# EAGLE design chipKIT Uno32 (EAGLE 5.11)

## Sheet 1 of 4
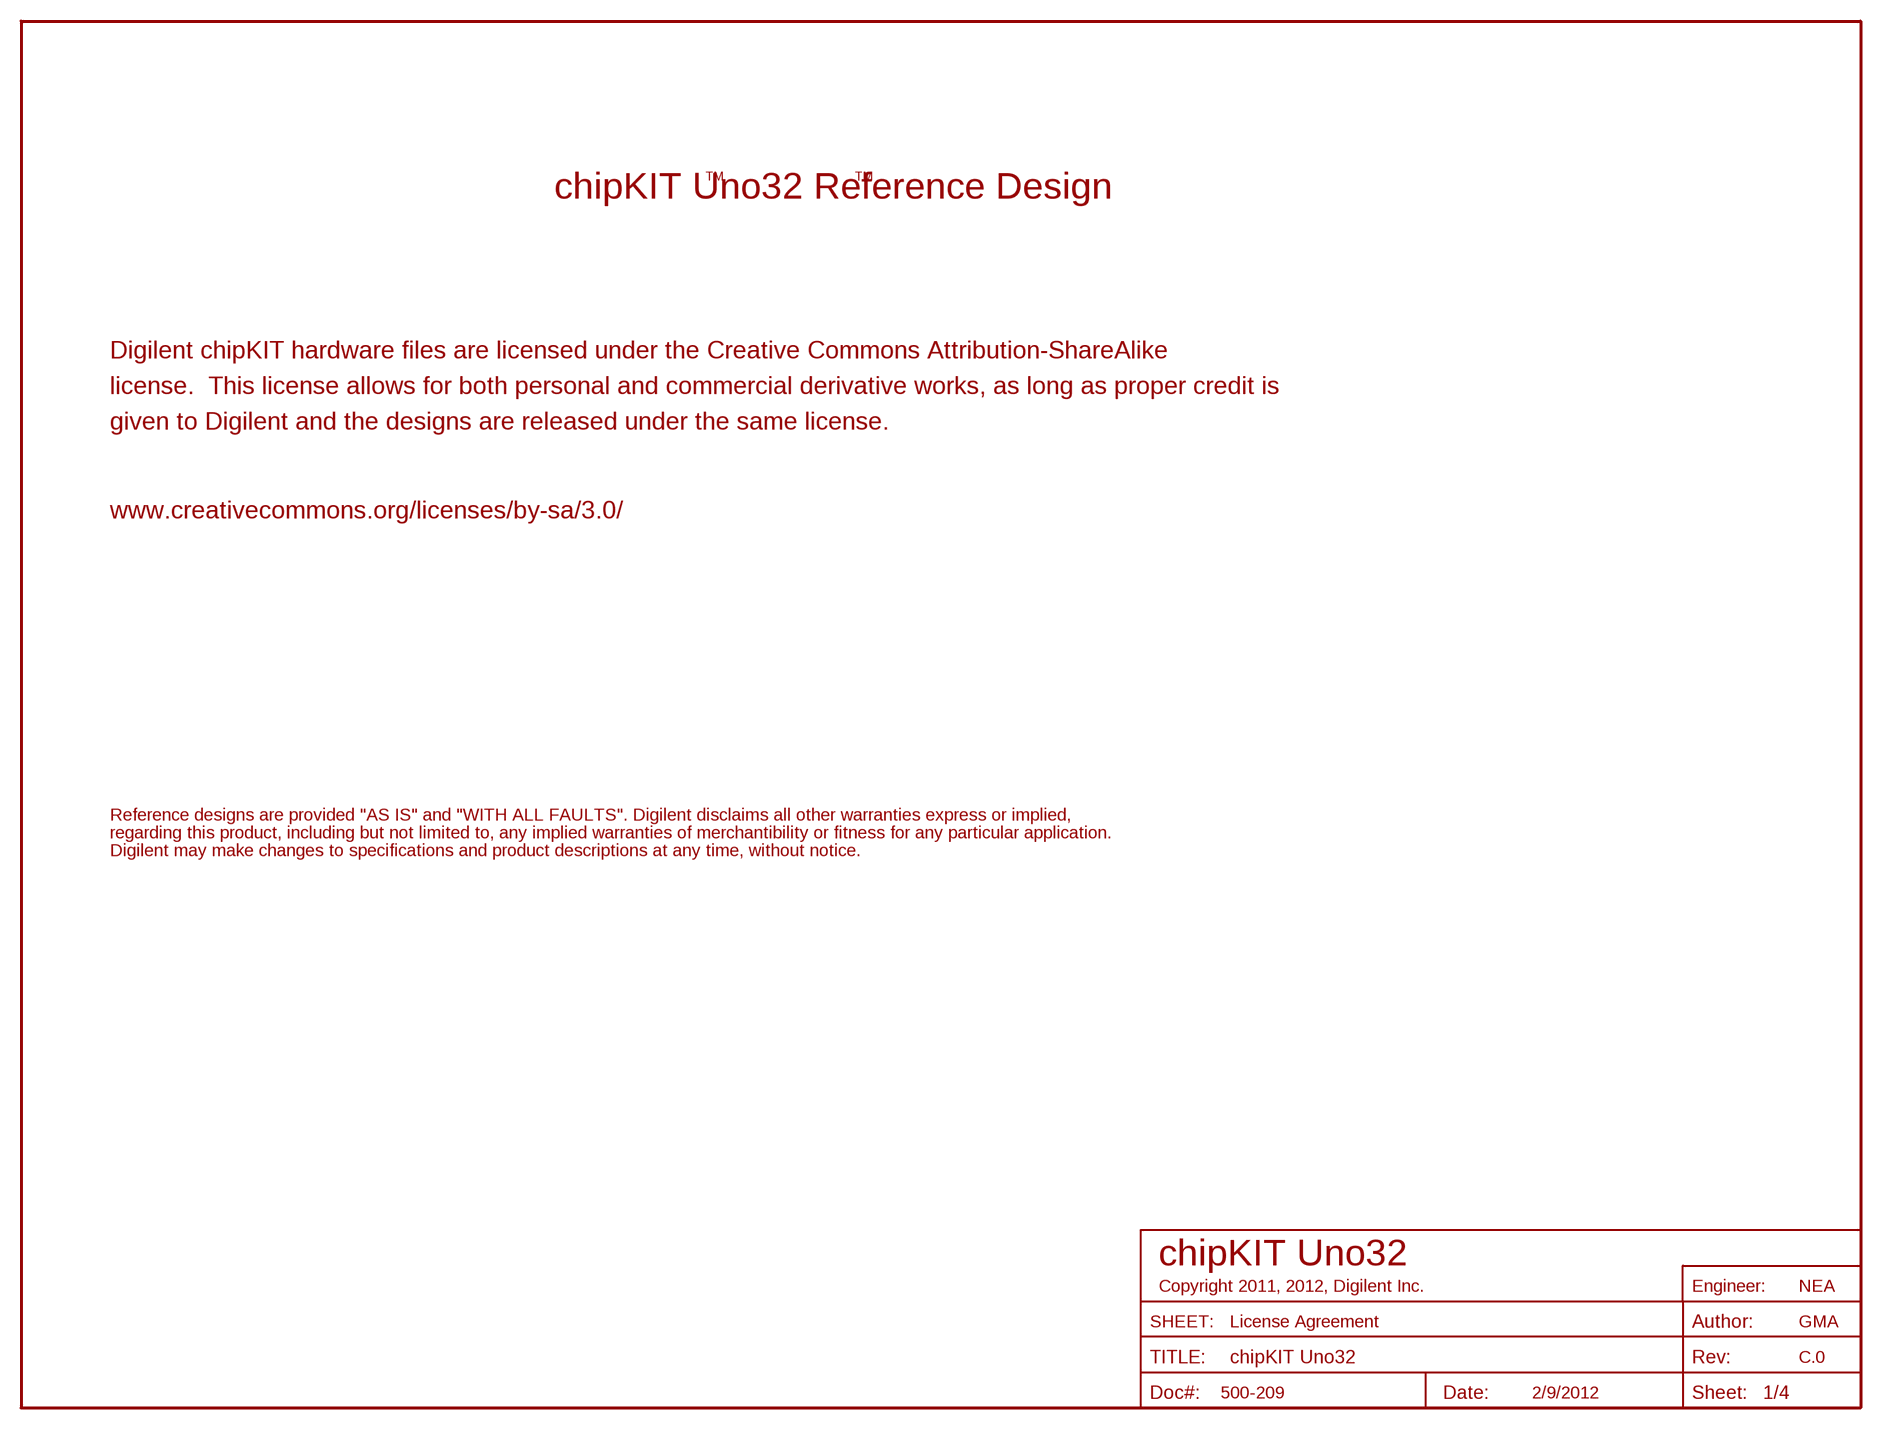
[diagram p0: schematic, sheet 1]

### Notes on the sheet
- TM | TM
- chipKIT Uno32 Reference Design
- Digilent chipKIT hardware files are licensed under the Creative Commons Attribution-ShareAlike
- license.  This license allows for both personal and commercial derivative works, as long as proper credit is
- given to Digilent and the designs are released under the same license.
- www.creativecommons.org/licenses/by-sa/3.0/
- Reference designs are provided "AS IS" and "WITH ALL FAULTS". Digilent disclaims all other warranties express or implied,
- regarding this product, including but not limited to, any implied warranties of merchantibility or fitness for any particular application.
- Digilent may make changes to specifications and product descriptions at any time, without notice.
- chipKIT Uno32
- Copyright 2011, 2012, Digilent Inc. | NEA
- License Agreement | GMA
- C.0
- 500-209 | 2/9/2012

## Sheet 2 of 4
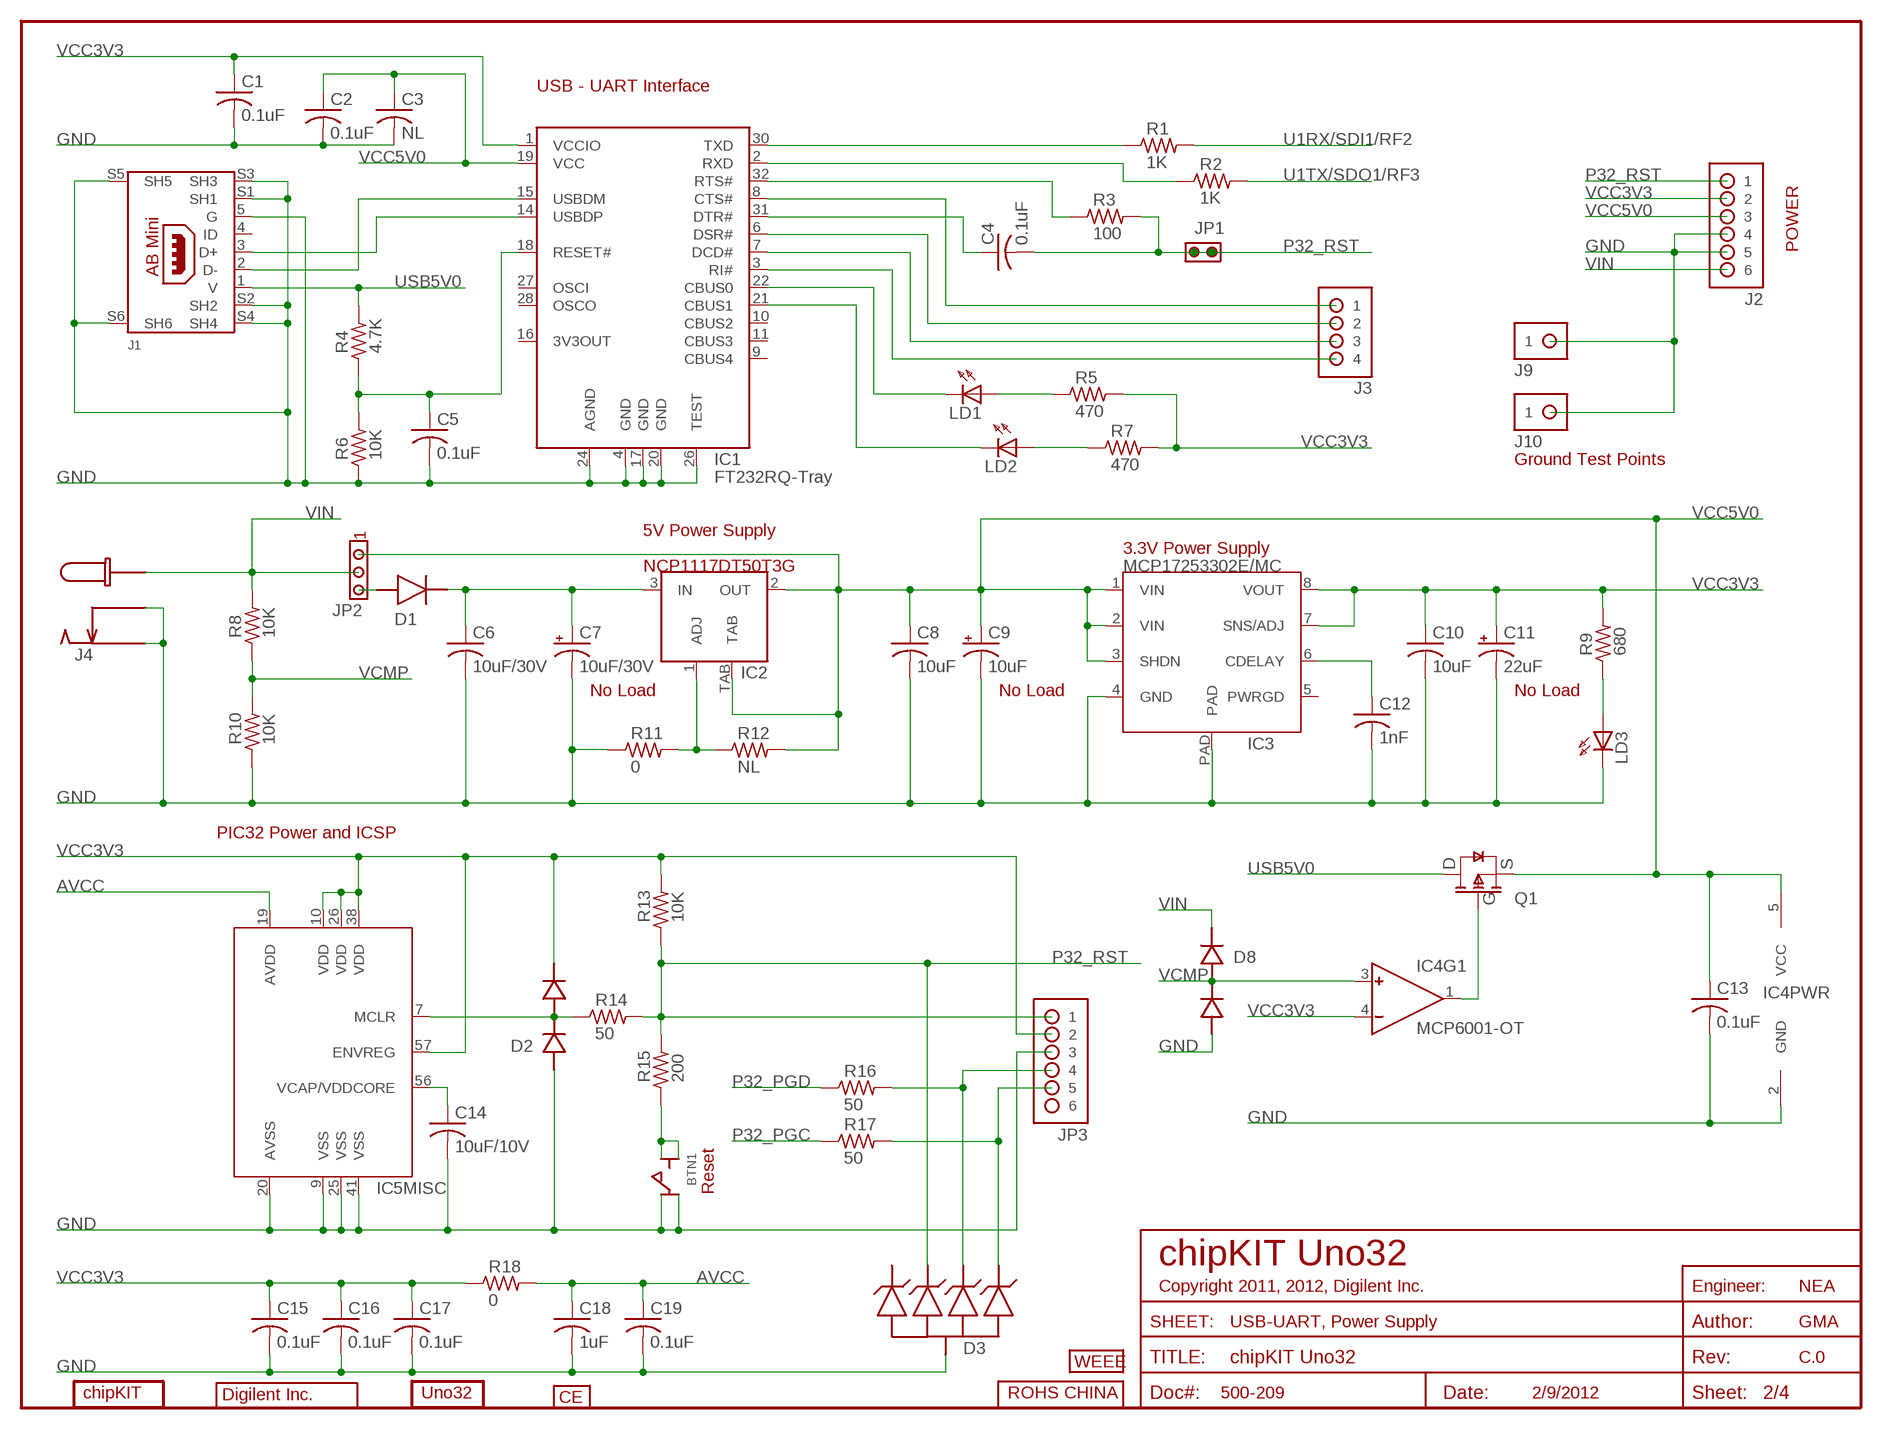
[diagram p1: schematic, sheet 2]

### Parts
BTN1  SW-P8008  [SW-P8008]
C1  0.1uF  CAP-S0402S  [C0402S]
C2  0.1uF  CAP-S0402S  [C0402S]
C3  NL  CAP-S0603S  [C0603S]
C4  0.1uF  CAP-S0402S  [C0402S]
C5  0.1uF  CAP-S0402S  [C0402S]
C6  10uF/30V  CAP-S0805S  [C0805S]
C7  10uF/30V  CPOL-SA  [CPOL3216]
C8  10uF  CAP-S0603S  [C0603S]
C9  10uF  CPOL-SA  [CPOL3216]
C10  10uF  CAP-S0603S  [C0603S]
C11  22uF  CPOL-SA  [CPOL3216]
C12  1nF  CAP-S0402S  [C0402S]
C13  0.1uF  CAP-S0402  [C0402]
C14  10uF/10V  CAP-S0603S  [C0603S]
C15  0.1uF  CAP-S0402S  [C0402S]
C16  0.1uF  CAP-S0402S  [C0402S]
C17  0.1uF  CAP-S0402S  [C0402S]
C18  1uF  CAP-S0402S  [C0402S]
C19  0.1uF  CAP-S0402S  [C0402S]
D1  B220A  DIODESMA  [SMA]
D2  BAV99W  [SOT-323]
D3  NSQA6V8  [SOT-323-5]
D8  BAV99W  [SOT-323]
IC1  FT232RQ-Tray  FT232RQ  [QFN32]
IC2  NCP1117DT50T3G  LM1117MP  [SOT223]
IC3  MCP17253302E/MC  MCP1725MC  [DFN8-MC]
IC4  MCP6001-OT  [SOT23-5-OT]
IC5  PIC32MX320F064H-80I/PT  PIC32MX340F512H-PT  [TQ64-PT]
J1  KMAB-SMT-5SS-30  USB-AB-MINI  [USB-AB-MINI]
J2  HDR-1X6  [HDR-1X6]
J3  HDR-1X4  [HDR-1X4]
J4  CON-COAX-KLD0202-S  [KLD-0202S]
J9  HDR-1X1  [HDR-1X1]
J10  HDR-1X1  [HDR-1X1]
JP1  No Load  JPR-1X2  [JPR-1X2]
JP2  JPR-1X3  [JPR-1X3]
JP3  HDR-1X6-OFFSET  [HDR-1X6_OFFSET]
LD1  LED-S0603-RED  LED-S0603  [D0603]
LD2  LED-S0603-RED  LED-S0603  [D0603]
LD3  LED-S0603-RED  LED-S0603  [D0603]
LOGO1  CE  [CE_LOGO]
LOGO2  WEEE-L  [WEEE_LOGO2]
LOGO3  ROHS-CHINA  [ROHS_CHINA_LOGO]
LOGO7  CHIPKIT  [CHIPKIT_LOGO]
LOGO8  DIGILENT_INC-BT-1500  [DIGILENT_BEYOND_1500_LOGO]
LOGO9  UNO32  [UNO32_LOGO]
Q1  FDN340P  [SOT23]
R1  1K  RES-S0402S  [R0402S]
R2  1K  RES-S0402S  [R0402S]
R3  100  RES-S0402S  [R0402S]
R4  4.7K  RES-S0402S  [R0402S]
R5  470  RES-S0402S  [R0402S]
R6  10K  RES-S0402S  [R0402S]
R7  470  RES-S0402S  [R0402S]
R8  10K  RES-S0402S  [R0402S]
R9  680  RES-S0402S  [R0402S]
R10  10K  RES-S0402S  [R0402S]
R11  0  RES-S0603S  [R0603S]
R12  NL  RES-S0402S  [R0402S]
R13  10K  RES-S0402S  [R0402S]
R14  50  RES-S0402S  [R0402S]
R15  200  RES-S0402S  [R0402S]
R16  50  RES-S0402S  [R0402S]
R17  50  RES-S0402S  [R0402S]
R18  0  RES-S0603S  [R0603S]

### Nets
AVCC: C18.1 C19.1 IC5.19(MISC:AVDD) R18.2
GND: BTN1.1A BTN1.2A C1.2 C2.2 C3.2 C5.2 C6.2 C7.- C8.2 C9.- C10.2 C11.- C12.2 C13.2 C14.2 C15.2 C16.2 C17.2 C18.2 C19.2 D2.1(CAT) D3.2(COM) D8.1(CAT) IC1.4(GND) IC1.17(GND) IC1.20(GND) IC1.24(AGND) IC1.26(TEST) IC3.4(GND) IC3.PAD IC4.2(PWR:GND) IC5.9(MISC:VSS) IC5.20(MISC:AVSS) IC5.25(MISC:VSS) IC5.41(MISC:VSS) J1.5(G) J1.S1(SH1) J1.S2(SH2) J1.S3(SH3) J1.S4(SH4) J1.S5(SH5) J1.S6(SH6) J2.4 J2.5 J4.2 J4.3 J9.1 J10.1 JP3.3 LD3.C R6.1 R10.1 R11.1 ; also sheet 3,4
N$1: IC1.14(USBDP) J1.3(D+)
N$2: IC1.15(USBDM) J1.2(D-)
N$3: C5.1 IC1.18(RESET#) R4.1 R6.2
N$4: IC1.30(TXD) R1.1
N$5: C14.1 IC5.56(MISC:VCAP/VDDCORE)
N$6: IC1.2(RXD) R2.1
N$7: D2.3(COM) IC5.7(MISC:MCLR) R14.1
N$8: C4.1 IC1.31(DTR#)
N$9: BTN1.1B BTN1.2B R15.1
N$10: IC1.8(CTS#) J3.1
N$11: D3.5(D4) JP3.5 R17.2
N$12: D3.4(D3) JP3.4 R16.2
N$13: IC1.6(DSR#) J3.2
N$14: IC1.7(DCD#) J3.3
N$15: IC1.3(RI#) J3.4
N$16: IC1.32(RTS#) R3.1
N$17: IC1.22(CBUS0) LD1.C
N$18: IC1.21(CBUS1) LD2.C
N$19: LD2.A R7.1
N$20: LD1.A R5.1
N$21: C12.1 IC3.6(CDELAY)
N$22: LD3.A R9.1
N$23: D1.A JP2.3
N$24: IC4.1(OUT) Q1.1(G)
N$26: C6.1 C7.+ D1.C IC2.3(IN)
N$49: IC2.1(ADJ) R11.2 R12.1
P32_PGC: R17.1 ; also sheet 3
P32_PGD: R16.1 ; also sheet 3
P32_RST: C4.2 D3.3(D2) J2.1 JP1.1 JP1.2 JP3.1 R3.2 R13.1 R14.2 R15.2
U1RX/SDI1/RF2: R1.2 ; also sheet 4
U1TX/SDO1/RF3: R2.2 ; also sheet 4
USB5V0: J1.1(V) Q1.3(D) R4.2
VCC3V3: C1.1 C10.1 C11.+ C15.1 C16.1 C17.1 D2.2(AN) IC1.1(VCCIO) IC3.7(SNS/ADJ) IC3.8(VOUT) IC4.4(IN-) IC5.10(MISC:VDD) IC5.26(MISC:VDD) IC5.38(MISC:VDD) IC5.57(MISC:ENVREG) J2.2 JP3.2 R5.2 R7.2 R9.2 R13.2 R18.1 ; also sheet 3,4
VCC5V0: C2.1 C3.1 C8.1 C9.+ C13.1 IC1.19(VCC) IC2.2(OUT) IC2.TAB IC3.1(VIN) IC3.2(VIN) IC3.3(SHDN) IC4.5(PWR:VCC) J2.3 JP2.1 Q1.2(S) R12.2
VCMP: D8.3(COM) IC4.3(IN+) R8.1 R10.2
VIN: D8.2(AN) J2.6 J4.1 JP2.2 R8.2
Unconnected: D3.1(D1) IC1.9(CBUS4) IC1.10(CBUS2) IC1.11(CBUS3) IC1.16(3V3OUT) IC1.27(OSCI) IC1.28(OSCO) IC3.5(PWRGD) J1.4(ID) JP3.6

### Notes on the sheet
- USB - UART Interface
- POWER
- Ground Test Points
- 5V Power Supply
- 3.3V Power Supply
- NCP1117DT50T3G
- No Load | No Load | No Load
- PIC32 Power and ICSP
- Reset
- chipKIT Uno32
- Copyright 2011, 2012, Digilent Inc. | NEA
- USB-UART, Power Supply | GMA
- C.0
- 500-209 | 2/9/2012

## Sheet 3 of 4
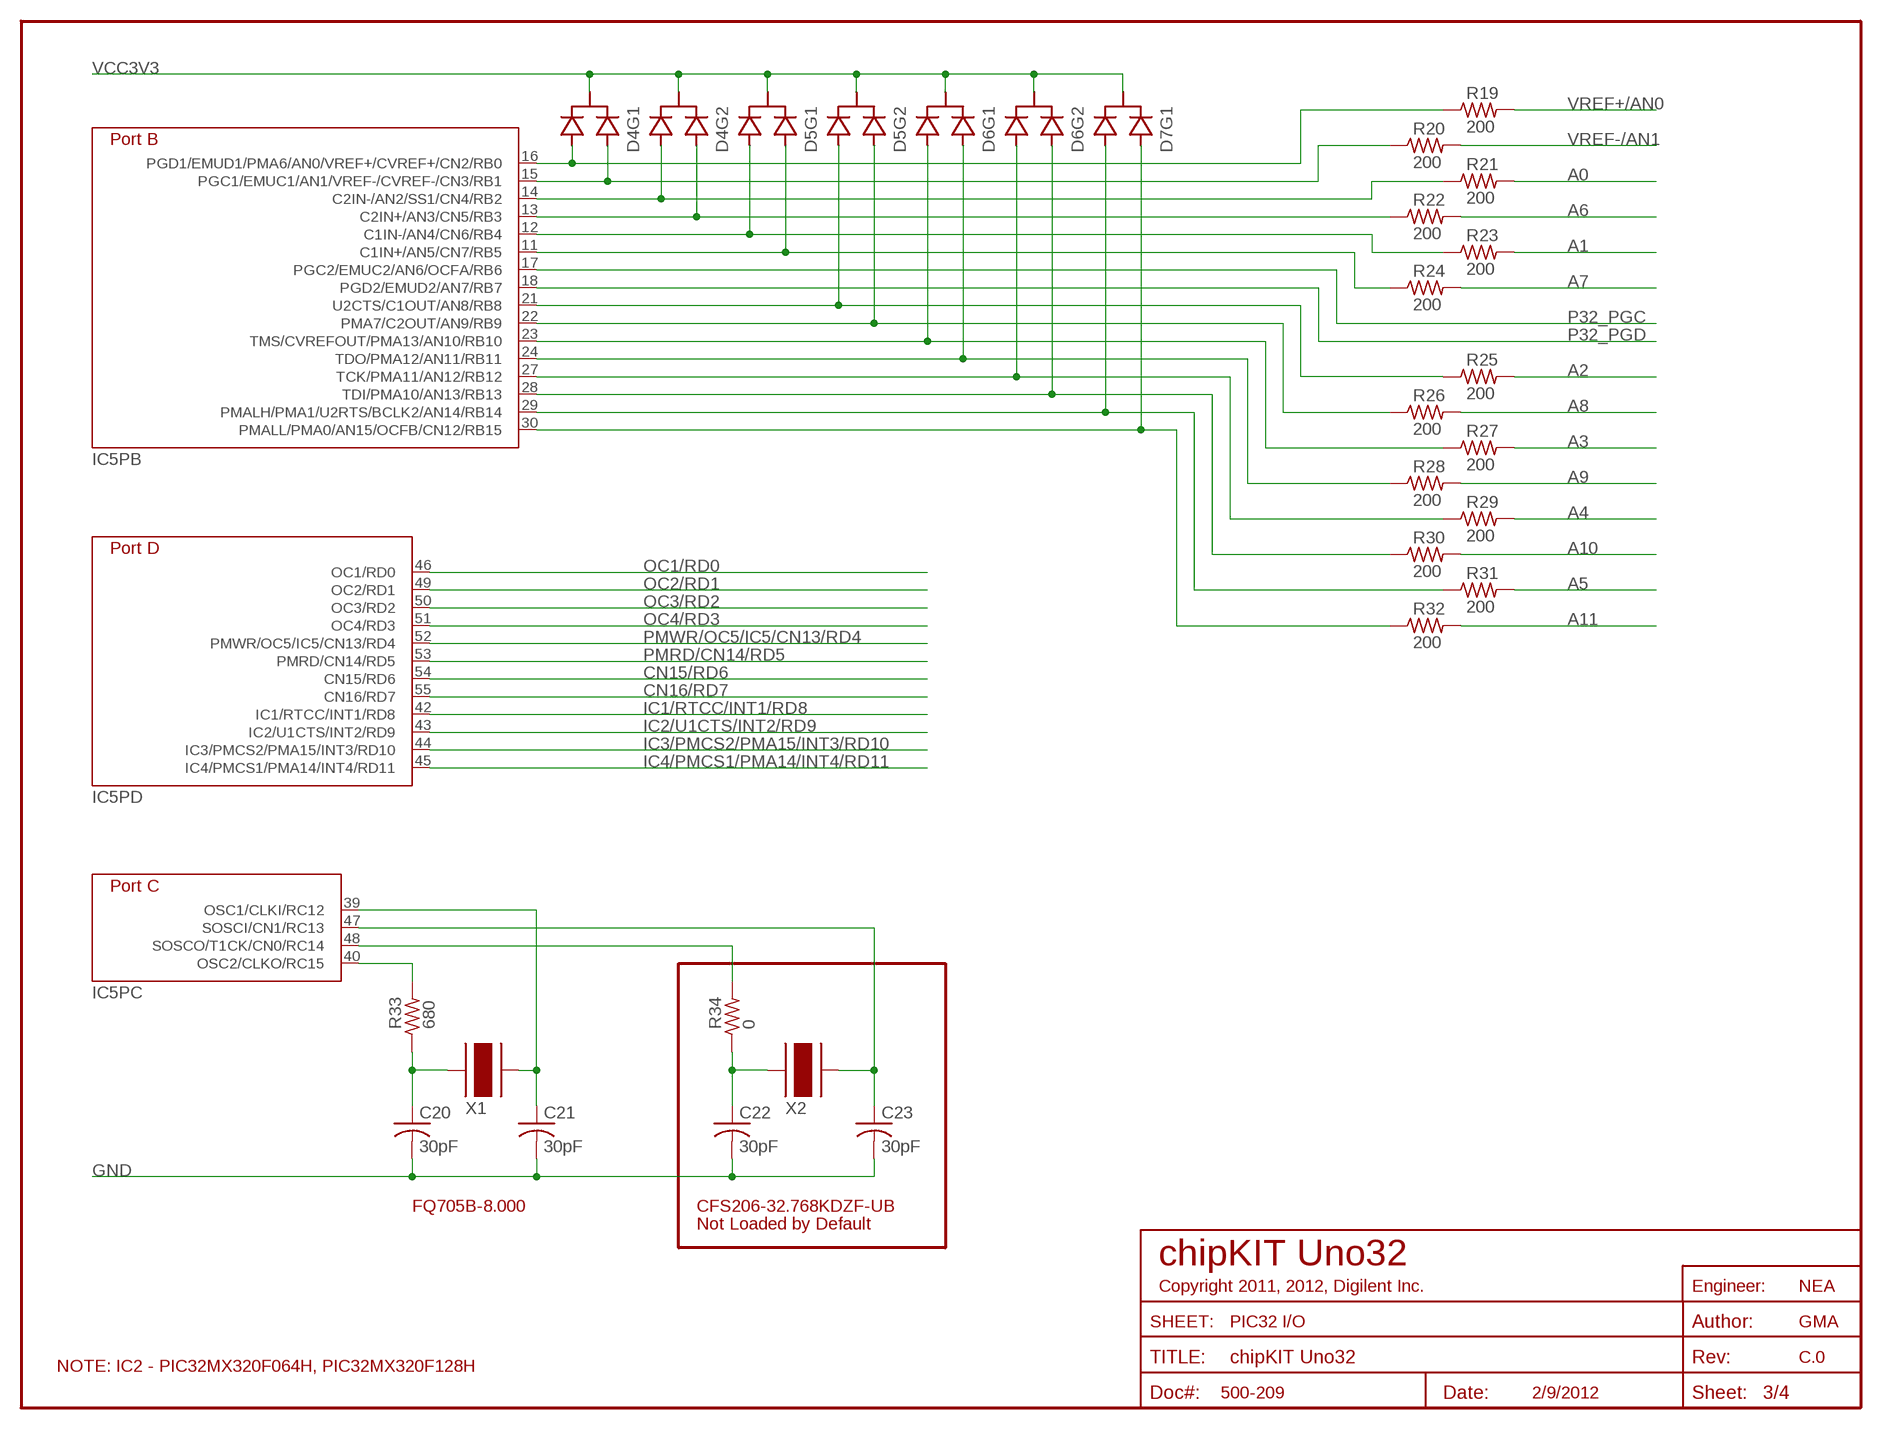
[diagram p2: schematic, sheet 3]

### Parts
C20  30pF  CAP-S0402S  [C0402S]
C21  30pF  CAP-S0402S  [C0402S]
C22  30pF  CAP-S0402S  [C0402S]
C23  30pF  CAP-S0402S  [C0402S]
D4  BAV70S  [SOT-363]
D5  BAV70S  [SOT-363]
D6  BAV70S  [SOT-363]
D7  BAV70S  [SOT-363]
R19  200  RES-S0402S  [R0402S]
R20  200  RES-S0402S  [R0402S]
R21  200  RES-S0402S  [R0402S]
R22  200  RES-S0402S  [R0402S]
R23  200  RES-S0402S  [R0402S]
R24  200  RES-S0402S  [R0402S]
R25  200  RES-S0402S  [R0402S]
R26  200  RES-S0402S  [R0402S]
R27  200  RES-S0402S  [R0402S]
R28  200  RES-S0402S  [R0402S]
R29  200  RES-S0402S  [R0402S]
R30  200  RES-S0402S  [R0402S]
R31  200  RES-S0402S  [R0402S]
R32  200  RES-S0402S  [R0402S]
R33  680  RES-S0402S  [R0402S]
R34  0  RES-S0402S  [R0402S]
X1  FQ705B-8.000  XTAL-FQ7050B  [FQ7050B]
X2  CFS206-32.768KDZF-UB  XTAL-T38  [XT-T38]

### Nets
A0: R21.2 ; also sheet 4
A1: R23.2 ; also sheet 4
A2: R25.2 ; also sheet 4
A3: R27.2 ; also sheet 4
A4: R29.2 ; also sheet 4
A5: R31.2 ; also sheet 4
A6: R22.2 ; also sheet 4
A7: R24.2 ; also sheet 4
A8: R26.2 ; also sheet 4
A9: R28.2 ; also sheet 4
A10: R30.2 ; also sheet 4
A11: R32.2 ; also sheet 4
CN15/RD6: IC5.54(PD:CN15/RD6) ; also sheet 4
CN16/RD7: IC5.55(PD:CN16/RD7) ; also sheet 4
GND: C20.2 C21.2 C22.2 C23.2 ; also sheet 2,4
IC1/RTCC/INT1/RD8: IC5.42(PD:IC1/RTCC/INT1/RD8) ; also sheet 4
IC2/U1CTS/INT2/RD9: IC5.43(PD:IC2/U1CTS/INT2/RD9) ; also sheet 4
IC3/PMCS2/PMA15/INT3/RD10: IC5.44(PD:IC3/PMCS2/PMA15/INT3/RD10) ; also sheet 4
IC4/PMCS1/PMA14/INT4/RD11: IC5.45(PD:IC4/PMCS1/PMA14/INT4/RD11) ; also sheet 4
N$28: C21.1 IC5.39(PC:OSC1/CLKI/RC12) X1.3
N$29: IC5.40(PC:OSC2/CLKO/RC15) R33.2
N$30: C20.1 R33.1 X1.1
N$31: IC5.48(PC:SOSCO/T1CK/CN0/RC14) R34.2
N$35: C22.1 R34.1 X2.1
N$38: D4.5(A2) IC5.13(PB:C2IN+/AN3/CN5/RB3) R22.1
N$39: D5.1(A1) IC5.12(PB:C1IN-/AN4/CN6/RB4) R23.1
N$40: D5.2(A2) IC5.11(PB:C1IN+/AN5/CN7/RB5) R24.1
N$41: D5.5(A2) IC5.22(PB:PMA7/C2OUT/AN9/RB9) R26.1
N$42: D6.1(A1) IC5.23(PB:TMS/CVREFOUT/PMA13/AN10/RB10) R27.1
N$43: D5.4(A1) IC5.21(PB:U2CTS/C1OUT/AN8/RB8) R25.1
N$44: C23.1 IC5.47(PC:SOSCI/CN1/RC13) X2.2
N$48: D4.4(A1) IC5.14(PB:C2IN-/AN2/SS1/CN4/RB2) R21.1
N$65: D4.1(A1) IC5.16(PB:PGD1/EMUD1/PMA6/AN0/VREF+/CVREF+/CN2/RB0) R19.1
N$66: D4.2(A2) IC5.15(PB:PGC1/EMUC1/AN1/VREF-/CVREF-/CN3/RB1) R20.1
N$67: D6.2(A2) IC5.24(PB:TDO/PMA12/AN11/RB11) R28.1
N$68: D6.4(A1) IC5.27(PB:TCK/PMA11/AN12/RB12) R29.1
N$69: D6.5(A2) IC5.28(PB:TDI/PMA10/AN13/RB13) R30.1
N$70: D7.1(A1) IC5.29(PB:PMALH/PMA1/U2RTS/BCLK2/AN14/RB14) R31.1
N$71: D7.2(A2) IC5.30(PB:PMALL/PMA0/AN15/OCFB/CN12/RB15) R32.1
OC1/RD0: IC5.46(PD:OC1/RD0) ; also sheet 4
OC2/RD1: IC5.49(PD:OC2/RD1) ; also sheet 4
OC3/RD2: IC5.50(PD:OC3/RD2) ; also sheet 4
OC4/RD3: IC5.51(PD:OC4/RD3) ; also sheet 4
P32_PGC: IC5.17(PB:PGC2/EMUC2/AN6/OCFA/RB6) ; also sheet 2
P32_PGD: IC5.18(PB:PGD2/EMUD2/AN7/RB7) ; also sheet 2
PMRD/CN14/RD5: IC5.53(PD:PMRD/CN14/RD5) ; also sheet 4
PMWR/OC5/IC5/CN13/RD4: IC5.52(PD:PMWR/OC5/IC5/CN13/RD4) ; also sheet 4
VCC3V3: D4.3(K) D4.6(K) D5.3(K) D5.6(K) D6.3(K) D6.6(K) D7.6(K) ; also sheet 2,4
VREF+/AN0: R19.2 ; also sheet 4
VREF-/AN1: R20.2 ; also sheet 4
Unconnected: D7.3(K) D7.4(A1) D7.5(A2)

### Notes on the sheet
- FQ705B-8.000 | CFS206-32.768KDZF-UB
- Not Loaded by Default
- chipKIT Uno32
- Copyright 2011, 2012, Digilent Inc. | NEA
- PIC32 I/O | GMA
- C.0
- NOTE: IC2 - PIC32MX320F064H, PIC32MX320F128H
- 500-209 | 2/9/2012

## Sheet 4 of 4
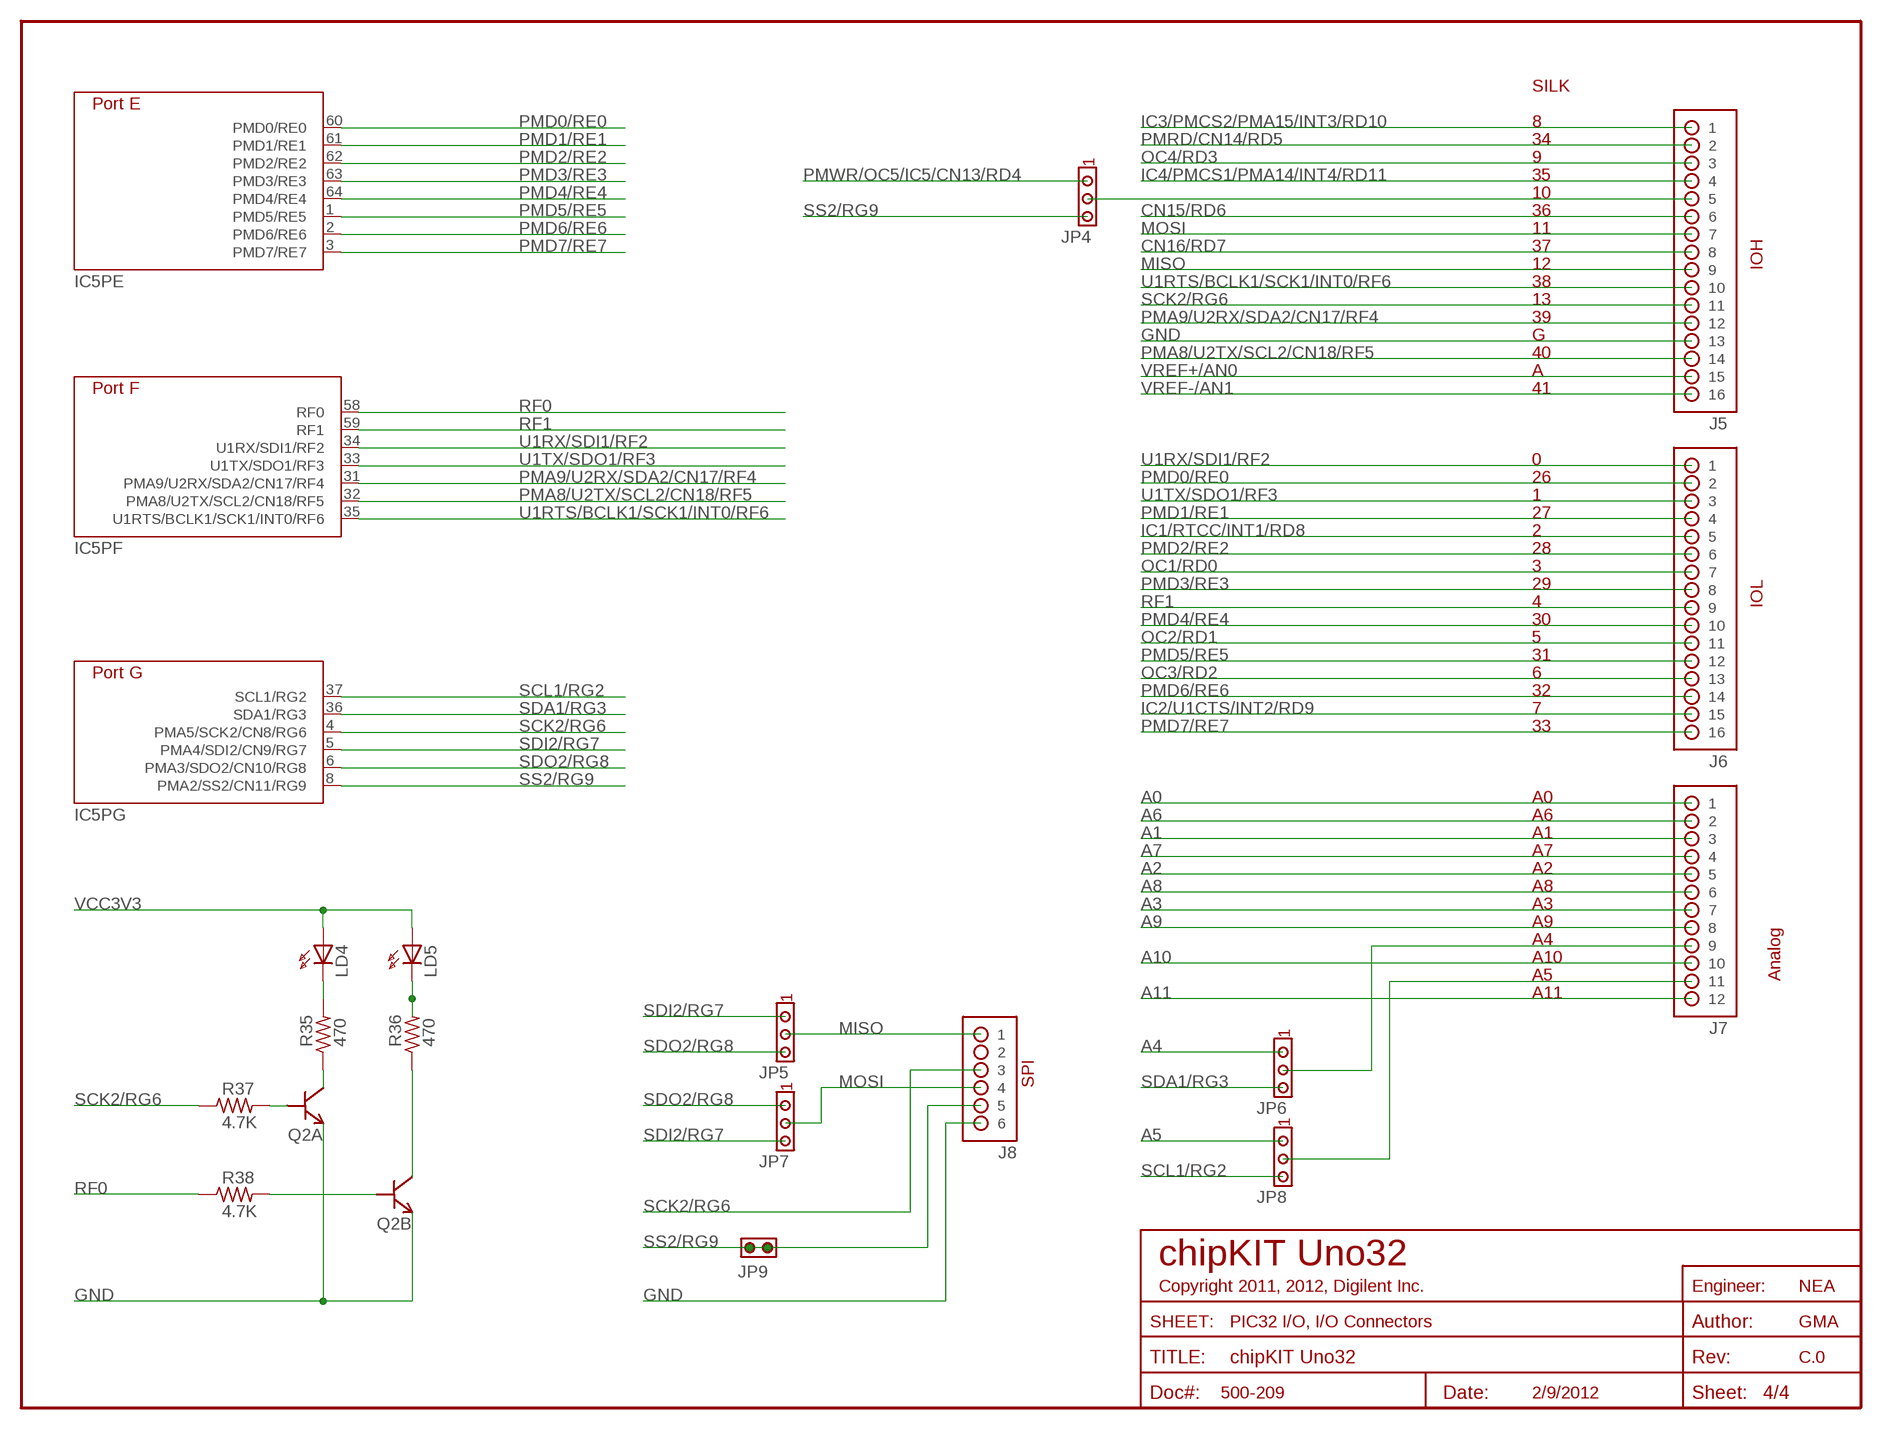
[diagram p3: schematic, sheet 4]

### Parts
J5  HDR-2X8  [HDR-2X8]
J6  HDR-2X8  [HDR-2X8]
J7  HDR-2X6  [HDR-2X6]
J8  HDR-2X3  [HDR-2X3]
JP4  JPR-1X3  [JPR-1X3]
JP5  JPR-1X3  [JPR-1X3]
JP6  JPR-1X3  [JPR-1X3]
JP7  JPR-1X3  [JPR-1X3]
JP8  JPR-1X3  [JPR-1X3]
JP9  JPR-1X2  [JPR-1X2]
LD4  LED-S0603-GRN  LED-S0603  [D0603]
LD5  LED-S0603-GRN  LED-S0603  [D0603]
Q2  MBT3904DW1T1  [SOT-363]
R35  470  RES-S0402S  [R0402S]
R36  470  RES-S0402S  [R0402S]
R37  4.7K  RES-S0402S  [R0402S]
R38  4.7K  RES-S0402S  [R0402S]

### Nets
A0: J7.1 ; also sheet 3
A1: J7.3 ; also sheet 3
A2: J7.5 ; also sheet 3
A3: J7.7 ; also sheet 3
A4: JP6.1 ; also sheet 3
A5: JP8.1 ; also sheet 3
A6: J7.2 ; also sheet 3
A7: J7.4 ; also sheet 3
A8: J7.6 ; also sheet 3
A9: J7.8 ; also sheet 3
A10: J7.10 ; also sheet 3
A11: J7.12 ; also sheet 3
CN15/RD6: J5.6 ; also sheet 3
CN16/RD7: J5.8 ; also sheet 3
GND: J5.13 J8.6 Q2.1(B:E) Q2.4(A:E) ; also sheet 2,3
IC1/RTCC/INT1/RD8: J6.5 ; also sheet 3
IC2/U1CTS/INT2/RD9: J6.15 ; also sheet 3
IC3/PMCS2/PMA15/INT3/RD10: J5.1 ; also sheet 3
IC4/PMCS1/PMA14/INT4/RD11: J5.4 ; also sheet 3
MISO: J5.9 J8.1 JP5.2
MOSI: J5.7 J8.4 JP7.2
N$25: J5.5 JP4.2
N$32: J7.9 JP6.2
N$33: J7.11 JP8.2
N$34: Q2.5(A:B) R37.2
N$36: LD4.C R35.2
N$37: Q2.3(A:C) R35.1
N$45: LD5.C R36.2
N$46: Q2.6(B:C) R36.1
N$47: Q2.2(B:B) R38.2
OC1/RD0: J6.7 ; also sheet 3
OC2/RD1: J6.11 ; also sheet 3
OC3/RD2: J6.13 ; also sheet 3
OC4/RD3: J5.3 ; also sheet 3
PMA8/U2TX/SCL2/CN18/RF5: IC5.32(PF:PMA8/U2TX/SCL2/CN18/RF5) J5.14
PMA9/U2RX/SDA2/CN17/RF4: IC5.31(PF:PMA9/U2RX/SDA2/CN17/RF4) J5.12
PMD0/RE0: IC5.60(PE:PMD0/RE0) J6.2
PMD1/RE1: IC5.61(PE:PMD1/RE1) J6.4
PMD2/RE2: IC5.62(PE:PMD2/RE2) J6.6
PMD3/RE3: IC5.63(PE:PMD3/RE3) J6.8
PMD4/RE4: IC5.64(PE:PMD4/RE4) J6.10
PMD5/RE5: IC5.1(PE:PMD5/RE5) J6.12
PMD6/RE6: IC5.2(PE:PMD6/RE6) J6.14
PMD7/RE7: IC5.3(PE:PMD7/RE7) J6.16
PMRD/CN14/RD5: J5.2 ; also sheet 3
PMWR/OC5/IC5/CN13/RD4: JP4.1 ; also sheet 3
RF0: IC5.58(PF:RF0) R38.1
RF1: IC5.59(PF:RF1) J6.9
SCK2/RG6: IC5.4(PG:PMA5/SCK2/CN8/RG6) J5.11 J8.3 R37.1
SCL1/RG2: IC5.37(PG:SCL1/RG2) JP8.3
SDA1/RG3: IC5.36(PG:SDA1/RG3) JP6.3
SDI2/RG7: IC5.5(PG:PMA4/SDI2/CN9/RG7) JP5.1 JP7.3
SDO2/RG8: IC5.6(PG:PMA3/SDO2/CN10/RG8) JP5.3 JP7.1
SS2/RG9: IC5.8(PG:PMA2/SS2/CN11/RG9) J8.5 JP4.3 JP9.1 JP9.2
U1RTS/BCLK1/SCK1/INT0/RF6: IC5.35(PF:U1RTS/BCLK1/SCK1/INT0/RF6) J5.10
U1RX/SDI1/RF2: IC5.34(PF:U1RX/SDI1/RF2) J6.1 ; also sheet 2
U1TX/SDO1/RF3: IC5.33(PF:U1TX/SDO1/RF3) J6.3 ; also sheet 2
VCC3V3: LD4.A LD5.A ; also sheet 2,3
VREF+/AN0: J5.15 ; also sheet 3
VREF-/AN1: J5.16 ; also sheet 3
Unconnected: J8.2

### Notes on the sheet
- SILK
- 8
- 34
- 9
- 35
- 10
- 36
- 11
- 37
- 12 | IOH
- 38
- 13
- 39
- G
- 40
- A
- 41
- 0
- 26
- 1
- 27
- 2
- 28
- 3
- 29
- 4 | IOL
- 30
- 5
- 31
- 6
- 32
- 7
- 33
- A0
- A6
- A1
- A7
- A2
- A8
- A3
- A9
- A4
- A10
- A5 | Analog
- A11
- SPI
- chipKIT Uno32
- Copyright 2011, 2012, Digilent Inc. | NEA
- PIC32 I/O, I/O Connectors | GMA
- C.0
- 500-209 | 2/9/2012

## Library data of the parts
BTN1 = Mechanical:SW-P8008: 153-000: SPST, Push button, momentary
C1-C6 C8 C10 C12-C23 = Discrete:CAP: Capacitor
C7 C9 C11 = Discrete:CPOL: Capacitor
D1 = Discrete:DIODE: Diode
D2 D8 = Discrete:BAV99W: BAV99W Dual Surface Mount Switching Diode
D3 = Discrete:NSQA6V8: Low Capacitance Quad ESD Protection Array
D4-D7 = Discrete:BAV70S: High Speed Switching Diode Array
IC1 = IC:FT232R: FTDI USB UART Serial Converter
IC2 = IC:LM1117: LM1117 Adjustable voltage regulator, 1.2V dropout
IC3 = Microchip:MCP1725MC: 500mA Low Voltage, Low Quiescent Current LDO Regulator
IC4 = Microchip:MCP6001: 1 Mhz Low Power Op Amp
IC5 = Microchip:PIC32MX340F*H: PIC32 64-Pin General Purpose 32-Bit Flash Microcontroller
J1 = Mechanical:USB-AB-MINI: Kycon KMAB-SMT-5S Mini USB AB type connector
J2 = Mechanical:HDR-1X6
J3 = Mechanical:HDR-1X4
J4 = Mechanical:CON-COAX: COAX Power Connector
J5 J6 = Mechanical:HDR-2X8: 100mil 2x8 header
J7 = Mechanical:HDR-2X6: 2x6 header with 42mil holes and 100mil spacing
J8 = Mechanical:HDR-2X3
J9 J10 = Mechanical:HDR-1X1
JP1 JP9 = Mechanical:JPR-1X2
JP2 JP4-JP8 = Mechanical:JPR-1X3
JP3 = Mechanical:HDR-1X6-OFFSET: 42 mil hole pattern with 16mil offset for jtag connector
LD1-LD5 = Discrete:LED: Discrete LED
LOGO1 = Logo:CE: European Union CE Logo
LOGO2 = Logo:WEEE: WEEE Symbol
LOGO3 = Logo:ROHS-CHINA: Chinese ROHS symbol logo
LOGO7 = Logo:CHIPKIT: Microchip chipKIT Logo
LOGO8 = Logo:DIGILENT_INC
LOGO9 = Logo:UNO32: Microchip chipKIT Uno32 Logo
Q1 = Discrete:FDN340P: Single P-channel, Logic Level, Power MOSFET
Q2 = Discrete:MBT3904DW1T1: On-Semiconductor MBT3904DW1T1 Dual General Purpose Transistors
R1-R38 = Discrete:RES: Resistor
X1 X2 = Discrete:XTAL: Quartz Crystal

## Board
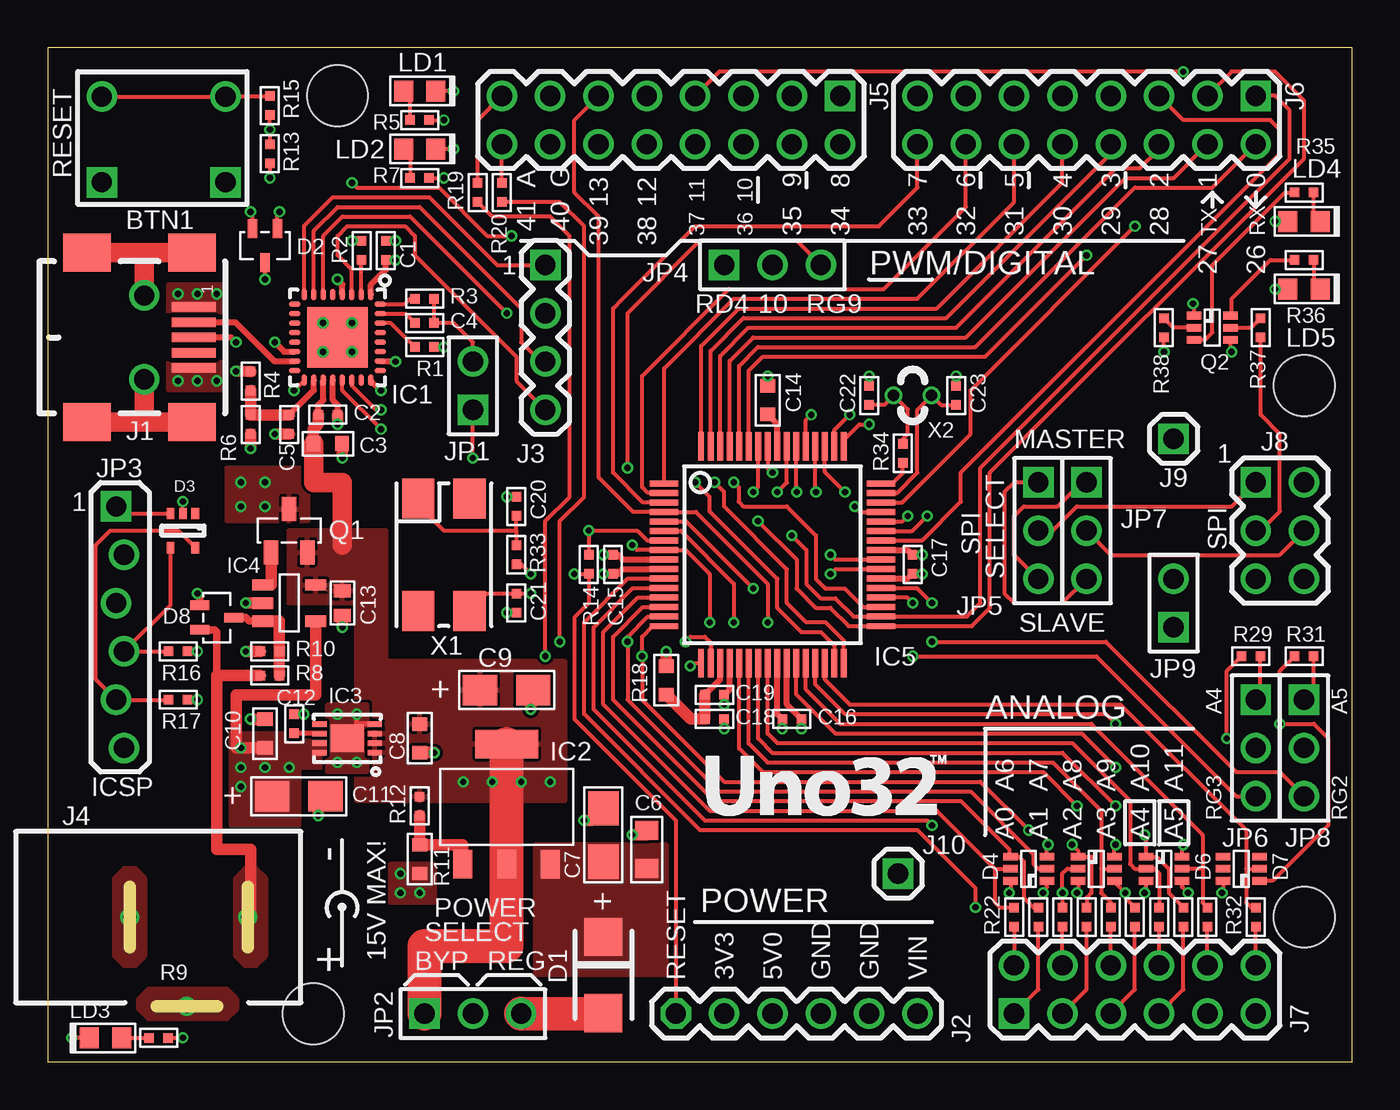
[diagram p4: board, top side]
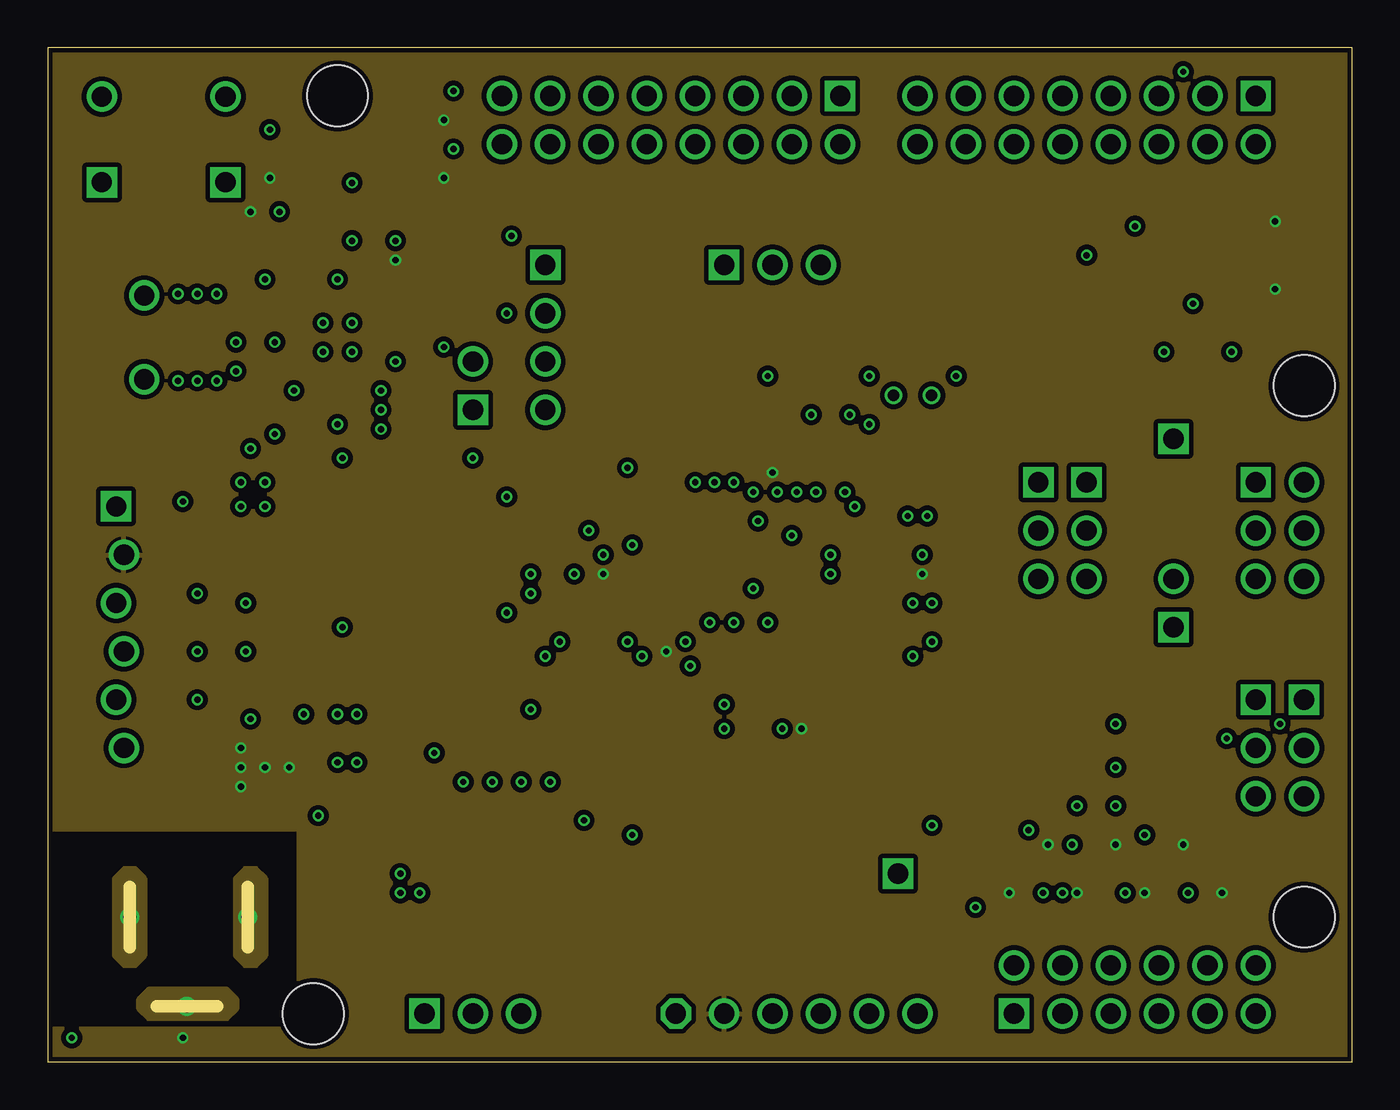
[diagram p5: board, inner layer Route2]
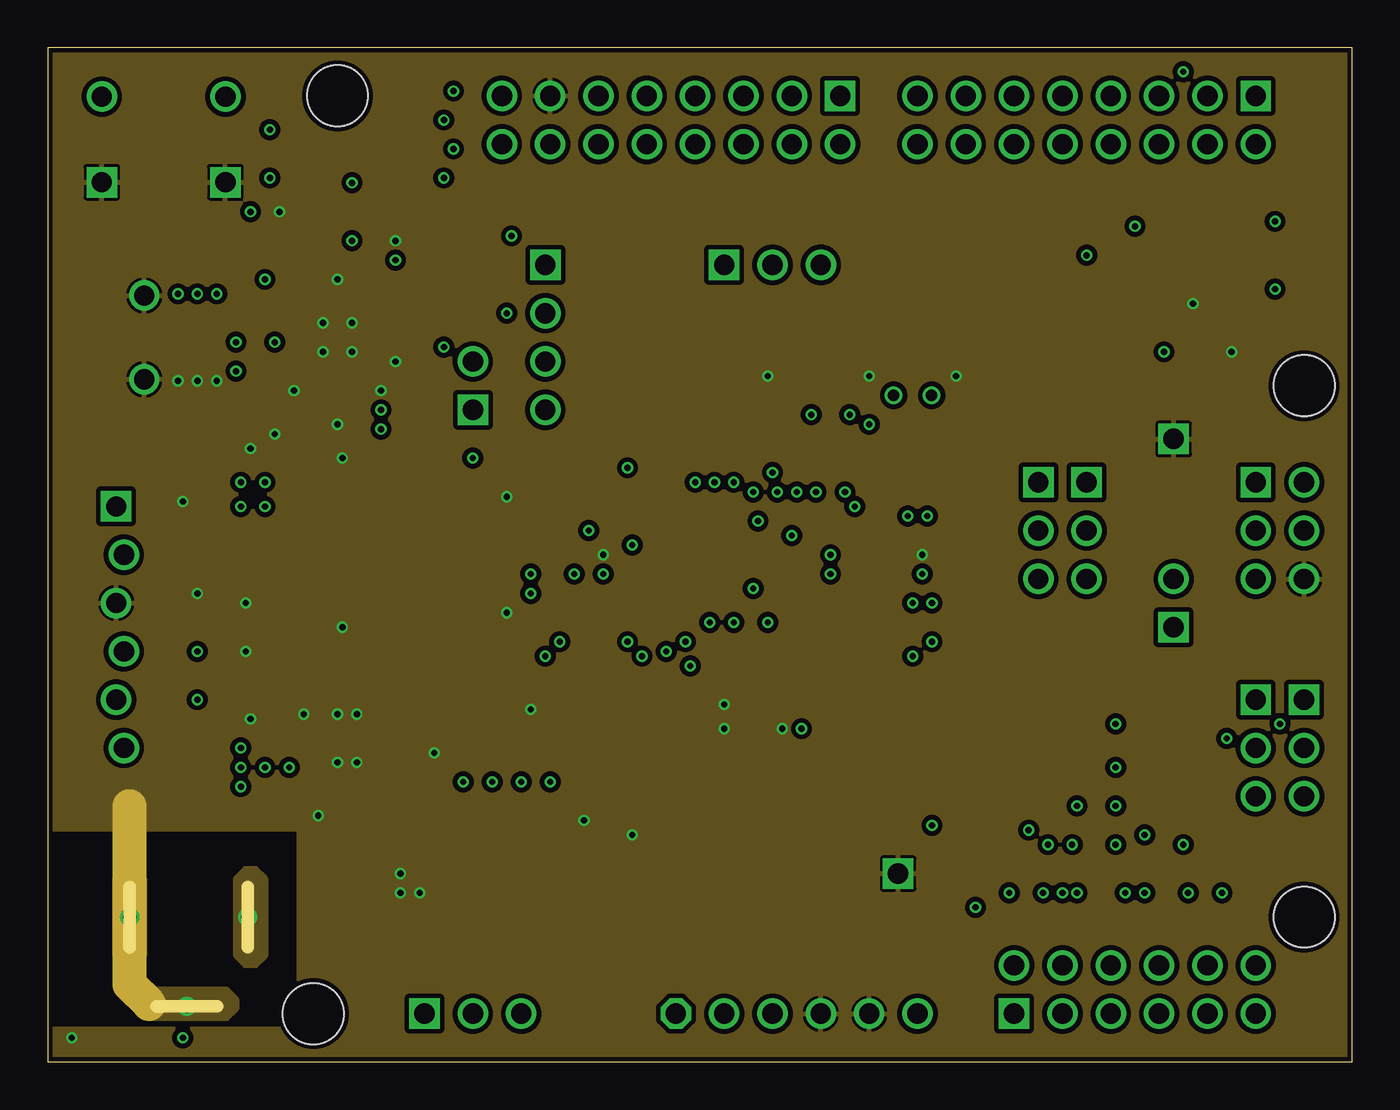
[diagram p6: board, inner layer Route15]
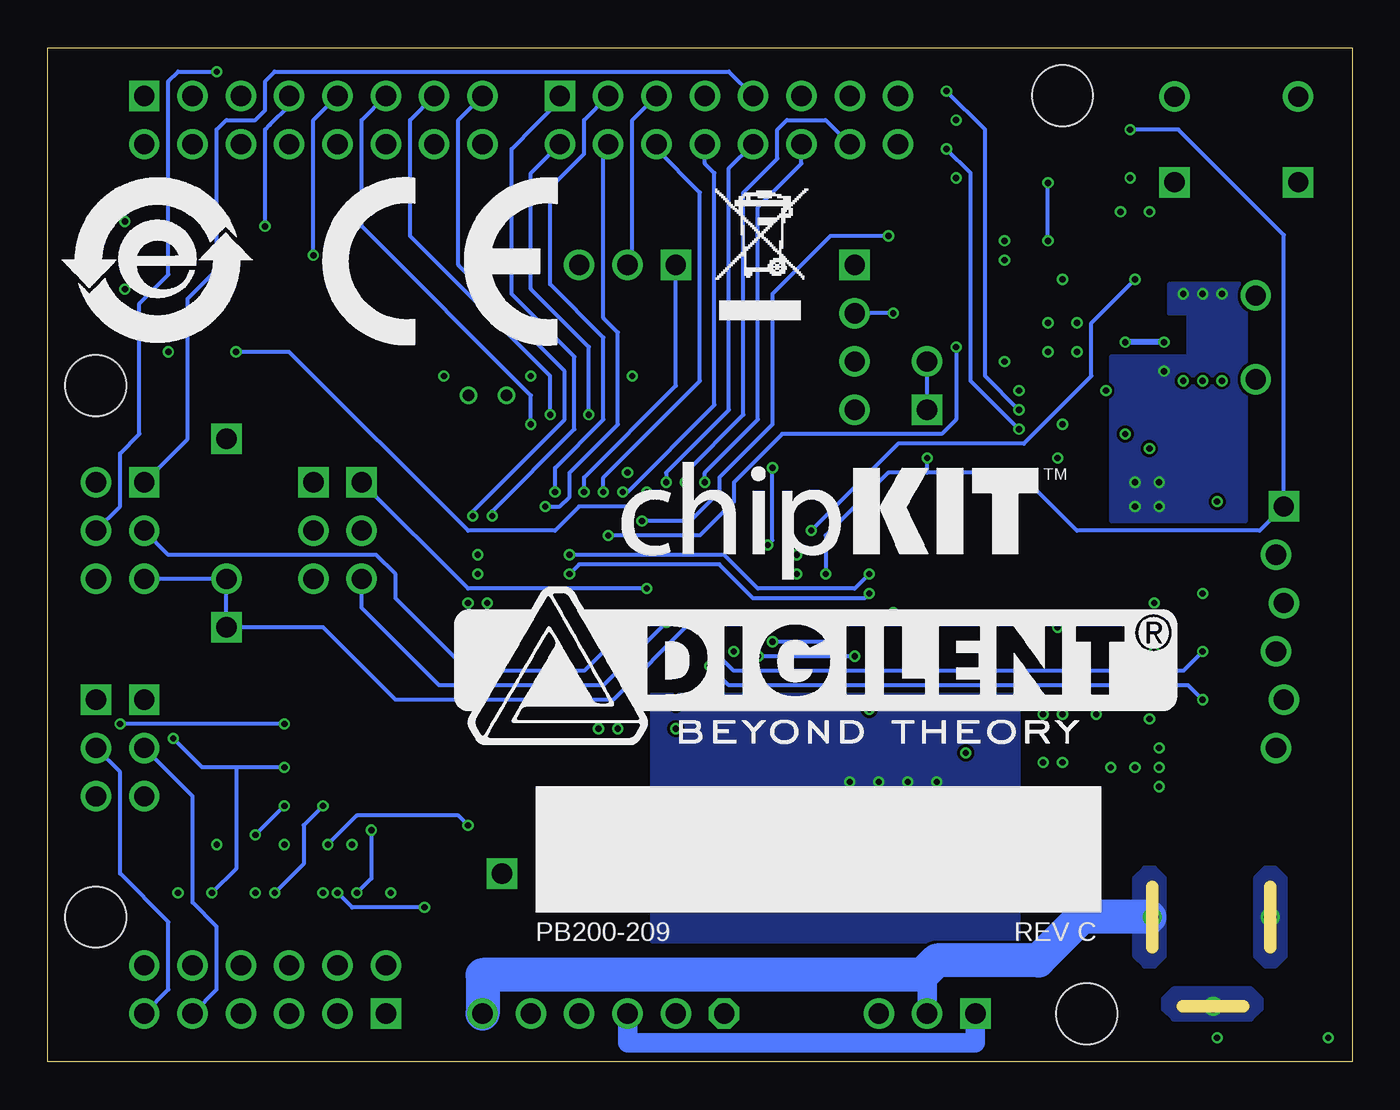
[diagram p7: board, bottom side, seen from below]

Size 68.58 x 53.34 mm. Coordinates in mm from the lower left corner, seen from the top.
Outline: 0,0 68.58,0 68.58,53.34 0,53.34 0,0
Copper layers (1+2*15+16): Top 0.035mm / dielectric 0.2mm / Route2 0.035mm / dielectric 0.2mm / Route15 0.035mm / dielectric 0.2mm / Bottom 0.035mm
Design rules "default *": minimum track width 8mil, minimum drill 0.3mm, track to track 6mil, track to pad 6mil, pad to pad 6mil, via to via 6mil, smd to smd 0mil, copper to edge 10mil, drill to drill 8mil, minimum pad ring 5mil, minimum via ring 5mil, stop-mask expansion 4mil, vias tented up to drill 15mil, thermal gap 6mil
Holes 3.2 mm at 15.24,50.8 66.04,35.56 66.04,7.62 13.97,2.54

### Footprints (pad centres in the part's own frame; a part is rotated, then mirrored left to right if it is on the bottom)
SW-P8008 = drill 1.067 square: 1A -2,3.5; 2A -2,-3 | drill 1.067 round: 1B 2.5,3.5; 2B 2.5,-3
C0402S = smd 0.5 x 0.5: 1 -0.5,0; 2 0.5,0
C0603S = smd 0.7 x 0.8: 1 -0.75,0; 2 0.75,0
C0805S = smd 1 x 1.2: 1 -1,0; 2 1,0
CPOL3216 = smd 1.8 x 1.6: + -1.4,0; - 1.4,0
C0402 = smd 0.7 x 0.9: 1 -0.65,0; 2 0.65,0
SMA = smd 2 x 2: A 2,0; C -2,0
SOT-323 = smd 0.5 x 1: 1 -0.65,-0.9; 2 0.65,-0.9; 3 0,0.9
SOT-323-5 = smd 0.4 x 0.6: 1 -0.65,-0.9; 2 0,-0.9; 3 0.65,-0.9; 4 0.65,0.9; 5 -0.65,0.9
SOT-363 = smd 0.4 x 0.762: 1 -0.635,-0.953; 2 0,-0.953; 3 0.635,-0.953; 4 0.635,0.953; 5 0,0.953; 6 -0.635,0.953
QFN32 = smd 0.6 x 0.3: 1 -2.25,1.75; 2 -2.25,1.25; 3 -2.25,0.75; 4 -2.25,0.25; 5 -2.25,-0.25; 6 -2.25,-0.75; 7 -2.25,-1.25; 8 -2.25,-1.75; 17 2.25,-1.75; 18 2.25,-1.25; 19 2.25,-0.75; 20 2.25,-0.25; 21 2.25,0.25; 22 2.25,0.75; 23 2.25,1.25; 24 2.25,1.75 | smd 0.3 x 0.6: 9 -1.75,-2.25; 10 -1.25,-2.25; 11 -0.75,-2.25; 12 -0.25,-2.25; 13 0.25,-2.25; 14 0.75,-2.25; 15 1.25,-2.25; 16 1.75,-2.25; 25 1.75,2.25; 26 1.25,2.25; 27 0.75,2.25; 28 0.25,2.25; 29 -0.25,2.25; 30 -0.75,2.25; 31 -1.25,2.25; 32 -1.75,2.25 | smd 3.2 x 3.2: PAD 0,0
SOT223 = smd 1 x 1.5: 1 -2.3,0; 2 0,0; 3 2.3,0 | smd 3.3 x 1.5: TAB 0,6.3
DFN8-MC = smd 0.3 x 0.75: 1 -0.75,-1.45; 2 -0.25,-1.45; 3 0.25,-1.45; 4 0.75,-1.45; 5 0.75,1.45; 6 0.25,1.45; 7 -0.25,1.45; 8 -0.75,1.45 | smd 1.45 x 1.75: PAD 0,0
SOT23-5-OT = smd 0.6 x 1.1: 1 -0.95,-1.4; 2 0,-1.4; 3 0.95,-1.4; 4 0.95,1.4; 5 -0.95,1.4
TQ64-PT = smd 1.5 x 0.3: 1 -5.7,3.75; 2 -5.7,3.25; 3 -5.7,2.75; 4 -5.7,2.25; 5 -5.7,1.75; 6 -5.7,1.25; 7 -5.7,0.75; 8 -5.7,0.25; 9 -5.7,-0.25; 10 -5.7,-0.75; 11 -5.7,-1.25; 12 -5.7,-1.75; 13 -5.7,-2.25; 14 -5.7,-2.75; 15 -5.7,-3.25; 16 -5.7,-3.75; 33 5.7,-3.75; 34 5.7,-3.25; 35 5.7,-2.75; 36 5.7,-2.25; 37 5.7,-1.75; 38 5.7,-1.25; 39 5.7,-0.75; 40 5.7,-0.25; 41 5.7,0.25; 42 5.7,0.75; 43 5.7,1.25; 44 5.7,1.75; 45 5.7,2.25; 46 5.7,2.75; 47 5.7,3.25; 48 5.7,3.75 | smd 0.3 x 1.5: 17 -3.75,-5.7; 18 -3.25,-5.7; 19 -2.75,-5.7; 20 -2.25,-5.7; 21 -1.75,-5.7; 22 -1.25,-5.7; 23 -0.75,-5.7; 24 -0.25,-5.7; 25 0.25,-5.7; 26 0.75,-5.7; 27 1.25,-5.7; 28 1.75,-5.7; 29 2.25,-5.7; 30 2.75,-5.7; 31 3.25,-5.7; 32 3.75,-5.7; 49 3.75,5.7; 50 3.25,5.7; 51 2.75,5.7; 52 2.25,5.7; 53 1.75,5.7; 54 1.25,5.7; 55 0.75,5.7; 56 0.25,5.7; 57 -0.25,5.7; 58 -0.75,5.7; 59 -1.25,5.7; 60 -1.75,5.7; 61 -2.25,5.7; 62 -2.75,5.7; 63 -3.25,5.7; 64 -3.75,5.7
USB-AB-MINI = smd 0.5 x 2.3: 1 -1.6,2.6; 2 -0.8,2.6; 3 0,2.6; 4 0.8,2.6; 5 1.6,2.6 | smd 2 x 2.5: S1 -4.45,2.5; S2 -4.45,-3; S3 4.45,-3; S4 4.45,2.5 | drill 1.067 round: S5 -2.2,0; S6 2.2,0
HDR-1X6 = drill 1.067 octagon: 1 0,6.35 | drill 1.067 round: 2 0,3.81; 3 0,1.27; 4 0,-1.27; 5 0,-3.81; 6 0,-6.35
HDR-1X4 = drill 1.067 square: 1 0,3.81 | drill 1.067 round: 2 0,1.27; 3 0,-1.27; 4 0,-3.81
KLD-0202S = drill 0.66 round: 1 6.2,0; 2 0,0; 3 3,-4.7
HDR-2X8 = drill 1.067 square: 1 -1.27,8.89 | drill 1.067 round: 2 1.27,8.89; 3 -1.27,6.35; 4 1.27,6.35; 5 -1.27,3.81; 6 1.27,3.81; 7 -1.27,1.27; 8 1.27,1.27; 9 -1.27,-1.27; 10 1.27,-1.27; 11 -1.27,-3.81; 12 1.27,-3.81; 13 -1.27,-6.35; 14 1.27,-6.35; 15 -1.27,-8.89; 16 1.27,-8.89
HDR-2X6 = drill 1.067 square: 1 -1.27,6.35 | drill 1.067 round: 2 1.27,6.35; 3 -1.27,3.81; 4 1.27,3.81; 5 -1.27,1.27; 6 1.27,1.27; 7 -1.27,-1.27; 8 1.27,-1.27; 9 -1.27,-3.81; 10 1.27,-3.81; 11 -1.27,-6.35; 12 1.27,-6.35
HDR-2X3 = drill 1.067 square: 1 -1.27,2.54 | drill 1.067 round: 2 1.27,2.54; 3 -1.27,0; 4 1.27,0; 5 -1.27,-2.54; 6 1.27,-2.54
HDR-1X1 = drill 1.067 square: 1 0,0
JPR-1X2 = drill 1.067 square: 1 0,1.27 | drill 1.067 round: 2 0,-1.27
JPR-1X3 = drill 1.067 square: 1 0,2.54 | drill 1.067 round: 2 0,0; 3 0,-2.54
HDR-1X6_OFFSET = drill 1.067 square: 1 -0.203,6.35 | drill 1.067 round: 2 0.203,3.81; 3 -0.203,1.27; 4 0.203,-1.27; 5 -0.203,-3.81; 6 0.203,-6.35
D0603 = smd 1 x 1.1: A 0.85,0; C -0.85,0
SOT23 = smd 0.762 x 1.27: 1 -0.953,-1.143; 2 0.953,-1.143; 3 0,1.143
R0402S = smd 0.5 x 0.5: 1 -0.5,0; 2 0.5,0
R0603S = smd 0.7 x 0.8: 1 -0.75,0; 2 0.75,0
FQ7050B = smd 2.1 x 1.7: 1 -2.95,-1.35; 2 2.95,-1.35; 3 2.95,1.35; 4 -2.95,1.35
XT-T38 = drill 0.61 round: 1 -1,0; 2 1,0

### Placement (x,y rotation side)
BTN1  6.35,48.26 90 top
C1  17.78,42.67 90 top
C2  14.73,34.04 0 top
C3  14.73,32.51 0 top
C4  19.81,38.86 0 top
C5  12.7,33.53 270 top
C6  31.5,11.18 90 top
C7  29.21,11.94 90 top
C8  19.56,17.02 270 top
C9  24.13,19.56 0 top
C10  11.43,17.27 90 top
C11  13.21,13.97 0 top
C12  12.95,17.78 90 top
C13  15.49,24.13 270 top
C14  37.85,34.8 90 top
C15  29.72,26.16 90 top
C16  39.12,18.03 180 top
C17  45.47,26.16 90 top
C18  35.05,18.03 0 top
C19  35.05,19.3 0 top
C20  24.64,29.21 90 top
C21  24.64,24.13 270 top
C22  43.18,35.05 90 top
C23  47.75,35.05 90 top
D1  29.21,4.57 270 top
D2  11.43,42.93 180 top
D3  7.11,27.94 180 top
D4  51.56,10.16 90 top
D5  55.12,10.16 270 top
D6  58.67,10.16 270 top
D7  62.74,10.16 90 top
D8  8.89,23.37 270 top
IC1  15.24,38.1 270 top
IC2  24.13,10.41 0 top
IC3  15.75,17.02 90 top
IC4  12.7,24.13 270 top
IC5  38.1,26.67 0 top
J1  5.08,38.1 270 top
J2  39.37,2.54 90 top
J3  26.16,38.1 0 top
J4  4.32,7.62 0 top
J5  32.77,49.53 270 top
J6  54.61,49.53 270 top
J7  57.15,3.81 90 top
J8  64.77,27.94 0 top
J9  59.18,32.77 0 top
J10  44.7,9.91 0 top
JP1  22.35,35.56 180 top
JP2  22.35,2.54 90 top
JP3  3.81,22.86 0 top
JP4  38.1,41.91 90 top
JP5  52.07,27.94 0 top
JP6  63.5,16.51 0 top
JP7  54.61,27.94 0 top
JP8  66.04,16.51 0 top
JP9  59.18,24.13 180 top
LD1  19.56,51.05 180 top
LD2  19.56,48.01 180 top
LD3  3.05,1.27 0 top
LD4  66.04,44.2 180 top
LD5  66.04,40.64 180 top
LOGO1  54.36,37.59 0 bottom
LOGO2  34.54,38.35 0 bottom
LOGO3  68.83,37.08 0 bottom
LOGO7  38.35,25.4 0 bottom
LOGO8  47.75,16.76 0 bottom
LOGO9  34.54,12.95 0 top
Q1  12.7,27.94 0 top
Q2  61.21,38.61 270 top
R1  19.81,37.59 0 top
R2  16.51,42.67 90 top
R3  19.81,40.13 0 top
R4  10.67,35.81 90 top
R5  19.56,49.53 0 top
R6  10.67,33.53 90 top
R7  19.56,46.48 0 top
R8  11.68,20.32 180 top
R9  5.84,1.27 0 top
R10  11.68,21.59 0 top
R11  19.56,10.67 90 top
R12  19.56,13.46 90 top
R13  11.68,47.75 270 top
R14  28.45,26.16 270 top
R15  11.68,50.29 270 top
R16  6.86,21.59 180 top
R17  6.86,19.05 180 top
R18  32.51,20.07 270 top
R19  22.61,45.72 90 top
R20  23.88,45.72 90 top
R21  52.07,7.62 270 top
R22  50.8,7.62 270 top
R23  54.61,7.62 270 top
R24  53.34,7.62 270 top
R25  57.15,7.62 270 top
R26  55.88,7.62 270 top
R27  59.69,7.62 270 top
R28  58.42,7.62 270 top
R29  63.25,21.34 0 top
R30  60.96,7.62 270 top
R31  66.04,21.34 0 top
R32  63.5,7.62 270 top
R33  24.64,26.67 270 top
R34  44.96,32 270 top
R35  66.04,45.72 0 top
R36  66.04,42.16 0 top
R37  63.75,38.61 90 top
R38  58.67,38.61 90 top
X1  20.83,26.67 270 top
X2  45.47,35.05 0 top

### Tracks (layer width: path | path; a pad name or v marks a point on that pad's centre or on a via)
A0
  Top 0.203: J7.1 52.07,3.81 R21.2
A1
  Top 0.203: J7.3 54.61,3.81 R23.2
A2
  Top 0.203: J7.5 57.15,3.81 R25.2
A3
  Top 0.203: J7.7 59.69,3.81 R27.2
A4
  Top 0.203: JP6.1 63.75,19.3 R29.2
A5
  Top 0.203: JP8.1 66.54,19.55 R31.2
A6
  Top 0.203: R22.2 J7.2
A7
  Top 0.203: J7.4 R24.2
A8
  Top 0.203: J7.6 R26.2
A9
  Top 0.203: J7.8 R28.2
A10
  Top 0.203: J7.10 R30.2
A11
  Top 0.203: J7.12 R32.2
AVCC
  Top 0.305: IC5.19 35.35,20.1 C19.1
  Top 0.61: C19.1 C18.1 33.79,18.03 R18.2
CN15/RD6  (via drill 0.33)
  Top 0.203: IC5.54 39.35,29.99 v39.37,29.97
  Bottom 0.203: v39.37,29.97 39.37,30.73 34.29,35.81 34.29,45.72 36.58,48.01 J5.6
CN16/RD7  (via drill 0.33)
  Top 0.203: IC5.55 38.85,30.47 v38.35,29.97
  Bottom 0.203: v38.35,29.97 38.1,29.97 33.53,34.54 33.53,46.74 34.04,47.24 J5.8
GND  (via drill 0.33)
  Top 0.203: C15.2 v29.22,26.66 v29.21,26.67 | D3.2 v7.11,29.46 | Q2.1 60.26,39.81 v60.2,39.88 | Q2.4 62.17,37.4 v62.23,37.34 | C23.2 v47.75,36.07 | C22.2 v43.18,36.07 | LD3.C v1.27,1.27 | IC1.17 v12.95,35.31 | D2.1 12.08,44.59 v12.19,44.7 | C21.2 v24.13,23.62 | C20.2 v24.14,29.71 v24.13,29.72
  Top 0.254: C12.2 v13.46,18.28 v13.46,18.29 | IC3.4 16.26,17.77 v16.26,18.29
  Top 0.305: IC5.9 30.22,26.42 29.97,26.67 C15.2 | v38.61,17.53 38.62,18.04 C16.2 38.35,18.3 IC5.25 | v45.97,26.67 v45.97,26.68 C17.2 45.21,26.92 IC5.41 | C14.2 v37.85,36.07 | v35.56,18.8 v35.55,18.8 C19.2 35.6,19.35 C19.2 35.85,19.59 IC5.20 | C18.2 v35.55,17.53 v35.56,17.53 | IC1.20 14.99,34.79 15.24,34.54 15.24,34.29 | 15.24,34.29 v15.24,33.53 | IC1.24 v17.53,35.31 | IC1.26 18.27,36.85 v18.29,36.83 | IC1.4 15.49,40.9 v15.24,41.15 | C1.2 v18.28,43.17 v18.29,43.18 | C3.2 15.49,32.5 | C2.2 15.23,34.28 15.24,34.29
  Top 0.406: D8.1 7.99,24.52 v7.87,24.64
  Top 0.61: C5.2 12.45,33.03 v11.94,33.02 | v15.24,33.53 C2.2 | v10.67,32.26 R6.1 | 15.49,32.5 v15.49,31.75 | C7.- 28.57,12.7 v28.19,12.7 | C6.2 31.48,11.94 v30.73,11.94 | C9.- 25.4,19.56 v25.4,18.54 | C8.2 v20.32,16.27 v20.32,16.26 | C10.2 v10.67,18.02 v10.67,18.03 | C11.- 14.22,13.97 v14.22,12.95 | C13.2 v15.49,22.86 | IC4.2 v10.41,24.13 | R10.1 v10.41,21.59
  Top 1.016: J1.S2 5.33,42.55 | 5.33,42.55 J1.S1 | J1.S3 5.08,33.65 | 5.08,33.65 J1.S4 | 5.08,33.65 J1.S6 | J1.S5 5.08,42.3 5.33,42.55
  Route15 1.778: 5.33,3.05 4.32,4.06 4.32,5.59 J4.2 4.32,13.46
  other vias: 14.48,38.86 16,38.86 14.48,37.34 16,37.34 8.89,35.81 7.87,35.81 6.86,35.81 18.54,9.91 18.54,8.89 19.56,8.89 15.24,18.29 15.24,15.75 16.26,15.75
  pour Route15 (isolate 0.254): 0,0 0,1.78 13.21,1.78 13.21,12.19 0,12.19 0,53.34 68.58,53.34 68.58,0
  pour Top (isolate 0.254, no thermals): 6.35,36.83 9.4,36.83 9.4,35.31 6.35,35.31
  pour Top (no thermals): 18.03,10.41 20.32,10.41 20.32,8.38 18.03,8.38
  pour Top (no thermals): 14.73,18.8 16.76,18.8 16.76,15.24 14.73,15.24
  pour Bottom (no thermals): 3.56,9.65 4.06,10.16 4.57,10.16 5.08,9.65 5.08,5.59 4.57,5.08 4.06,5.08 3.56,5.59
  pour Route15 (no thermals): 3.56,9.65 4.06,10.16 4.57,10.16 5.08,9.65 5.08,5.59 4.57,5.08 4.06,5.08 3.56,5.59
  pour Top (no thermals): 3.56,9.65 4.06,10.16 4.57,10.16 5.08,9.65 5.08,5.59 4.57,5.08 4.06,5.08 3.56,5.59
  pour Route2 (no thermals): 3.56,5.59 3.56,9.65 4.06,10.16 4.57,10.16 5.08,9.65 5.08,5.59 4.57,5.08 4.06,5.08
  pour Route2 (no thermals): 9.4,2.29 5.33,2.29 4.83,2.79 4.83,3.3 5.33,3.81 9.4,3.81 9.91,3.3 9.91,2.79
  pour Bottom (no thermals): 5.33,2.29 4.83,2.79 4.83,3.3 5.33,3.81 9.4,3.81 9.91,3.3 9.91,2.79 9.4,2.29
  pour Route15 (no thermals): 5.33,2.29 4.83,2.79 4.83,3.3 5.33,3.81 9.4,3.81 9.91,3.3 9.91,2.79 9.4,2.29
  pour Top (no thermals): 5.33,2.29 4.83,2.79 4.83,3.3 5.33,3.81 9.4,3.81 9.91,3.3 9.91,2.79 9.4,2.29
IC1/RTCC/INT1/RD8
  Top 0.203: IC5.42 45.96,27.42 48.01,29.46 48.01,30.99 64.77,47.75 64.77,49.02 64.26,49.53 59.69,49.53 J6.5
IC2/U1CTS/INT2/RD9  (via drill 0.33)
  Top 0.203: IC5.43 45.45,27.92 v46.23,28.7
  Bottom 0.203: v46.23,28.7 46.23,28.96 41.4,33.78 41.4,36.32 46.99,41.91 46.99,49.53 J6.15
IC3/PMCS2/PMA15/INT3/RD10  (via drill 0.33)
  Top 0.203: IC5.44 44.93,28.42 v45.21,28.7
  Bottom 0.203: J5.1 41.66,50.55 42.93,49.28 44.2,48.01 44.2,40.39 40.89,37.08 40.89,33.27 45.21,28.96 v45.21,28.7
IC4/PMCS1/PMA14/INT4/RD11  (via drill 0.33)
  Top 0.203: IC5.45 42.71,28.92 v42.42,29.21
  Bottom 0.203: J5.4 39.37,48.01 39.37,39.12 38.61,38.35 38.61,33.53 41.15,30.99 41.15,29.72 41.66,29.21 v42.42,29.21
MISO
  Top 0.203: J8.1 62.23,29.21 54.1,29.21 52.83,27.94 JP5.2
  Bottom 0.203: J5.9 32.77,52.07 56.64,52.07 57.15,51.56 57.15,50.04 57.66,49.53 59.18,49.53 59.69,49.02 59.69,41.66 61.21,40.13 61.21,32.77 J8.1
MOSI  (via drill 0.33)
  Top 0.203: J8.4 64.77,26.67 55.88,26.67 JP7.2 | J5.7 35.31,52.07 v59.69,52.07
  Bottom 0.203: v59.69,52.07 61.72,52.07 62.23,51.56 62.23,41.4 63.75,39.88 63.75,33.02 64.77,32 64.77,29.21 J8.4
N$1  (via drill 0.33)
  Top 0.305: IC1.14 12.43,37.35 v11.94,37.85 | v9.91,37.85 9.65,38.1 J1.3
  Bottom 0.305: v9.91,37.85 v11.94,37.85
N$2
  Top 0.305: IC1.15 11.92,36.85 9.87,38.9 J1.2
N$3
  Top 0.305: IC1.18 13.99,35.33 C5.1
  Top 0.61: C5.1 R6.2 R4.1
N$4
  Top 0.203: IC1.30 18.05,38.85 18.8,38.1 R1.1
N$5
  Top 0.305: IC5.56 38.35,33.54 C14.1
N$6
  Top 0.203: IC1.2 16.49,42.15 R2.1
N$7  (via drill 0.33)
  Top 0.203: IC5.7 31.51,27.42 30.99,27.94 v28.45,27.94 R14.1 | v11.43,41.15 D2.3
  Bottom 0.203: v11.43,41.15 13.72,38.86 13.72,36.07 17.27,32.51 23.88,32.51 v28.45,27.94
N$8
  Top 0.203: IC1.31 18.82,39.35 C4.1
N$9
  Top 0.203: BTN1.1B BTN1.2B 9.38,50.79 R15.1
N$10
  Top 0.203: IC1.8 13.49,43.97 14.99,45.47 20.07,45.47 23.62,41.91 J3.1
N$11
  Top 0.203: D3.5 6.86,27.94 3.3,27.94 2.54,27.18 2.54,20.12 JP3.5 R17.2
N$12
  Top 0.203: R16.2 JP3.4 6.46,24.04 D3.4
N$13  (via drill 0.33)
  Top 0.203: IC1.6 14.49,43.45 15.49,44.45 19.05,44.45 v24.13,39.37
  Bottom 0.203: v24.13,39.37 J3.2
N$14
  Top 0.203: IC1.7 13.99,43.71 15.24,44.96 19.56,44.96 24.89,39.62 24.89,37.85 25.91,36.83 J3.3
N$15
  Top 0.203: IC1.3 15.99,41.67 15.24,42.42 15.24,43.43 15.75,43.94 18.8,43.94 19.3,43.43 19.3,42.42 24.64,37.08 24.64,35.81 J3.4
N$16
  Top 0.203: IC1.32 18.77,39.85 19.05,40.13 R3.1
N$17  (via drill 0.33)
  Top 0.203: IC1.22 15.99,35.57 17.27,34.29 v17.53,34.29 | v21.34,51.05 LD1.C
  Bottom 0.203: v17.53,34.29 19.3,36.07 19.3,49.02 v21.34,51.05
N$18  (via drill 0.33)
  Top 0.203: IC1.21 15.49,35.31 v17.53,33.27 | v21.34,48.01 LD2.C
  Bottom 0.203: v17.53,33.27 20.07,35.81 20.07,46.74 v21.34,48.01
N$19
  Top 0.203: R7.1 19.06,47.66 LD2.A
N$20
  Top 0.203: R5.1 19.06,50.7 LD1.A
N$21
  Top 0.254: IC3.6 12.95,17.27 C12.1
N$22
  Top 0.203: LD3.A R9.1
N$23
  Top 1.778: JP2.3 D1.A
N$24
  Top 0.61: IC4.1 11.75,25.08 Q1.1
N$25
  Bottom 0.203: J5.5 37.85,49.53 37.85,42.16 JP4.2
N$26
  pour Top (no thermals): 25.65,11.43 32.51,11.43 32.51,4.57 25.65,4.57
N$28  (via drill 0.33)
  Top 0.203: IC5.39 41.41,25.92 v41.15,25.65 | X1.3 23.09,24.63 C21.1 v25.39,24.63 v25.4,24.64
  Bottom 0.203: v41.15,25.65 40.64,26.16 33.27,26.16 31.5,24.38 25.65,24.38 v25.4,24.64
N$29  (via drill 0.33)
  Top 0.203: IC5.40 41.4,26.42 v41.15,26.67 | R33.2 24.88,26.17 v25.4,25.65
  Bottom 0.203: v41.15,26.67 33.02,26.67 31.24,24.89 26.16,24.89 v25.4,25.65
N$30
  Top 0.203: X1.1 19.48,29.29 20.83,27.94 24.64,27.94 | 24.64,27.94 R33.1 | 24.64,27.94 C20.1
N$31
  Top 0.203: R34.2 44.95,30.98 44.45,30.48 43.86,30.48 IC5.48
N$32
  Bottom 0.203: J7.9 59.69,3.81 59.69,7.11 60.96,8.38 60.96,13.97 JP6.2
N$33
  Bottom 0.203: J7.11 62.23,3.81 62.23,7.37 64.77,9.91 64.77,15.24 JP8.2
N$34
  Top 0.203: Q2.5 63.25,38.61 R37.2
N$35
  Top 0.203: R34.1 44.96,32.77 45.21,33.02 45.21,34.31 X2.1 43.97,34.55 C22.1
N$36
  Top 0.203: LD4.C 66.54,44.55 R35.2
N$37
  Top 0.203: R35.1 65.02,45.72 61.21,41.91 61.21,38.35 60.83,37.97 Q2.3
N$38
  Top 0.203: IC5.13 31.02,24.42 29.21,22.61 29.21,18.8 34.8,13.21 46.74,13.21 49.78,10.16 | 49.78,10.16 D4.5 | R22.1 50.05,8.12 49.78,8.38 49.78,10.16
N$39  (via drill 0.33)
  Top 0.203: R23.1 54.61,8.64 54.86,8.89 54.86,10.79 D5.1 54.17,11.11 v53.85,11.43 | IC5.12 30.76,24.92 28.7,22.86 28.7,18.54 34.54,12.7 46.23,12.7 v46.48,12.45
  Bottom 0.203: v46.48,12.45 46.99,12.95 52.32,12.95 v53.85,11.43
N$40  (via drill 0.33)
  Top 0.203: R24.1 v53.34,8.89 53.34,9.91 53.59,10.16 D5.2 | IC5.11 30.5,25.42 28.19,23.11 28.19,18.29 34.29,12.19 45.72,12.19 48.77,9.14 v48.77,8.13
  Bottom 0.203: v48.77,8.13 52.58,8.13 v53.34,8.89
N$41
  Top 0.203: R26.1 55.88,8.38 55.37,8.89 55.37,10.16 | 55.37,10.16 D5.5 | IC5.22 36.85,16.74 37.85,15.75 52.83,15.75 55.37,13.21 55.37,10.16
N$42  (via drill 0.33)
  Top 0.203: R27.1 58.93,8.89 58.93,10.16 58.29,10.79 D6.1 57.72,11.87 v57.66,11.94 | IC5.23 37.35,17.01 38.1,16.26 53.34,16.26 v56.13,13.46
  Bottom 0.203: v56.13,13.46 v57.66,11.94
N$43  (via drill 0.33)
  Top 0.203: IC5.21 36.35,16.48 37.59,15.24 52.32,15.24 v54.1,13.46 | R25.1 56.64,8.63 v56.64,8.89 56.07,9.46 D5.4
  Bottom 0.203: v54.1,13.46 55.12,12.45 55.12,10.41 v56.64,8.89
N$44
  Top 0.203: IC5.47 44.65,29.92 45.72,30.99 45.72,34.29 46.48,35.05 X2.2 46.97,34.55 C23.1
N$45
  Top 0.203: LD5.C 66.8,40.73 66.8,40.89 66.54,41.16 R36.2
N$46
  Top 0.203: R36.1 64.26,42.16 62.23,40.13 62.23,39.31 Q2.6
N$47
  Top 0.203: Q2.2 59.17,38.61 R38.2
N$48
  Top 0.203: R21.1 51.81,8.13 51.31,8.63 51.31,10.54 51.05,10.79 D4.4 50.55,10.86 50.55,11.18 48.01,13.72 35.05,13.72 29.72,19.05 29.72,22.35 31.29,23.92 IC5.14
N$49
  Top 0.61: IC2.1 21.83,11.42 R11.2 R12.1
N$65  (via drill 0.33)
  Top 0.203: IC5.16 31.81,22.92 31.24,22.35 v31.24,21.34 31.24,19.05 35.56,14.73 49.02,14.73 v51.56,12.19 | D4.1 52.51,9.21 v52.32,8.89 | R19.1 23.38,44.45 26.42,44.45 27.43,43.43 27.43,29.72 26.16,28.45 v26.16,21.34
  Bottom 0.203: v51.56,12.19 51.56,9.65 v52.32,8.89 | v26.16,21.34 v31.24,21.34
N$66  (via drill 0.33)
  Top 0.203: IC5.15 31.55,23.42 30.48,22.35 v30.48,22.1 30.48,19.05 35.31,14.22 48.51,14.22 51.82,10.92 51.82,10.41 52.07,10.16 D4.2 | R20.1 26.92,45.22 28.19,43.94 28.19,29.72 26.92,28.45 v26.92,22.1
  Bottom 0.203: v26.92,22.1 v30.48,22.1
N$67
  Top 0.203: R28.1 58.42,9.91 58.17,10.16 D6.2 57.15,10.16 56.9,10.41 56.9,13.72 53.85,16.76 38.35,16.76 37.85,17.27 IC5.24
N$68  (via drill 0.33)
  Top 0.203: IC5.27 39.35,19.32 41.4,17.27 54.36,17.27 v56.13,15.49 | D6.4 59.63,9.21 v59.94,8.89 | R29.1 61.98,20.57 v61.98,17.02
  Bottom 0.203: v59.94,8.89 58.67,10.16 58.67,15.49 | v61.98,17.02 60.45,15.49 58.67,15.49 | v56.13,15.49 58.67,15.49
N$69
  Top 0.203: 60.71,10.16 D6.5 | 60.71,10.16 60.71,8.37 R30.1 | IC5.28 39.85,19.59 41.66,17.78 54.86,17.78 60.71,11.94 60.71,10.16
N$70  (via drill 0.33)
  Top 0.203: D7.1 64.39,9.53 67.31,12.45 67.31,17.02 66.55,17.78 v64.77,17.78 64.77,20.57 R31.1 | IC5.29 40.35,19.85 41.91,18.29 55.63,18.29 v56.13,17.78
  Bottom 0.203: v56.13,17.78 v64.77,17.78
N$71
  Top 0.203: R32.1 63.25,8.12 62.99,8.38 62.99,10.16 | IC5.30 40.85,20.11 42.16,18.8 56.39,18.8 62.99,12.19 62.99,10.16 | 62.99,10.16 D7.2 63.75,10.16
OC1/RD0  (via drill 0.33)
  Top 0.203: IC5.46 44.91,29.42 48.51,33.02 48.51,35.31 v57.15,43.94
  Bottom 0.203: v57.15,43.94 57.15,49.02 56.9,49.28 55.88,50.29 J6.7
OC2/RD1  (via drill 0.33)
  Top 0.203: IC5.49 41.85,32.71 42.67,33.53 v43.18,33.53
  Bottom 0.203: v43.18,33.53 43.18,35.05 52.07,43.94 52.07,49.53 J6.11
OC3/RD2  (via drill 0.33)
  Top 0.203: IC5.50 41.35,33.22 v42.16,34.04
  Bottom 0.203: v42.16,34.04 42.16,36.07 49.53,43.43 49.53,49.53 J6.13
OC4/RD3  (via drill 0.33)
  Top 0.203: IC5.51 40.85,31.03 v41.91,29.97
  Bottom 0.203: v41.91,29.97 41.91,31.24 39.37,33.78 39.37,38.1 42.16,40.89 42.16,45.97 40.39,47.75 40.39,49.53 J5.3
P32_PGC  (via drill 0.33)
  Top 0.203: IC5.17 33.92,20.97 v33.78,20.83 | R17.1 v7.87,19.05
  Bottom 0.203: v33.78,20.83 32.77,19.81 8.64,19.81 v7.87,19.05
P32_PGD  (via drill 0.33)
  Top 0.203: IC5.18 34.85,22.05 34.54,22.35 33.78,22.35 v33.53,22.1 | R16.1 v7.87,21.59
  Bottom 0.203: v33.53,22.1 33.53,21.59 32.51,20.57 8.89,20.57 v7.87,21.59
P32_RST  (via drill 0.33)
  Top 0.203: R3.2 C4.2 21.34,38.86 22.35,37.85 JP1.2 | 11.69,48.26 R13.1 v11.68,49.02 R15.2 | J2.1 33.02,12.7 27.69,18.03 27.69,23.37 28.45,24.13 R14.2 v27.69,25.65 | v22.35,31.75 JP1.1 | D3.3 3.98,28.84 JP3.1
  Bottom 0.203: v27.69,25.65 27.69,27.69 24.38,30.99 22.35,30.99 | v11.68,49.02 9.14,49.02 3.61,43.48 JP3.1 | JP1.1 JP1.2 | 22.35,30.99 v22.35,31.75 | 22.35,30.99 17.53,30.99 14.48,27.94 4.88,27.94 JP3.1 | JP3.1 3.61,29.41
PMA8/U2TX/SCL2/CN18/RF5  (via drill 0.33)
  Top 0.203: IC5.32 41.85,22.16 40.89,23.11 39.88,23.11 38.86,24.13 38.86,25.91 35.56,29.21 35.56,29.97 v35.05,30.48
  Bottom 0.203: v35.05,30.48 35.05,30.99 32,34.04 32,45.72 30.23,47.5 30.23,49.02 29.72,49.53 27.69,49.53 J5.14
PMA9/U2RX/SDA2/CN17/RF4  (via drill 0.33)
  Top 0.203: IC5.31 41.35,21.9 40.64,22.61 39.62,22.61 38.35,23.88 38.35,25.4 34.8,28.96 34.8,29.72 v34.04,30.48
  Bottom 0.203: v34.04,30.48 34.04,30.99 31.24,33.78 31.24,44.96 28.96,47.24 J5.12
PMD0/RE0
  Top 0.203: IC5.60 36.35,36.6 37.34,37.59 48.77,37.59 57.15,45.97 61.21,45.97 J6.2
PMD1/RE1
  Top 0.203: IC5.61 35.85,36.87 37.08,38.1 48.26,38.1 56.64,46.48 59.18,46.48 J6.4
PMD2/RE2
  Top 0.203: IC5.62 35.35,37.13 36.83,38.61 47.75,38.61 56.13,46.99 57.4,46.99 58.42,48.01 J6.6
PMD3/RE3
  Top 0.203: IC5.63 34.85,37.39 36.58,39.12 47.24,39.12 55.88,47.75 J6.8
PMD4/RE4
  Top 0.203: IC5.64 34.35,37.65 36.32,39.62 46.74,39.62 53.34,46.23 J6.10
PMD5/RE5
  Top 0.203: IC5.1 32.4,36.46 36.07,40.13 45.72,40.13 50.8,45.21 J6.12
PMD6/RE6
  Top 0.203: IC5.2 31.55,29.92 31.24,30.23 31.24,36.07 35.81,40.64 43.94,40.64 48.26,44.96 J6.14
PMD7/RE7
  Top 0.203: IC5.3 31.29,29.42 29.72,30.99 29.72,39.62 30.23,40.13 34.04,43.94 43.69,43.94 45.72,45.97 J6.16
PMRD/CN14/RD5  (via drill 0.33)
  Top 0.203: IC5.53 39.85,33.75 v40.13,34.04
  Bottom 0.203: v40.13,34.04 40.13,37.59 43.18,40.64 43.18,46.74 J5.2
PMWR/OC5/IC5/CN13/RD4  (via drill 0.33)
  Top 0.203: IC5.52 40.35,30.19 v40.39,29.97
  Bottom 0.203: v40.39,29.97 40.39,30.73 35.56,35.56 JP4.1
RF0  (via drill 0.33)
  Top 0.203: IC5.58 37.35,30.24 v37.08,29.97 | v58.67,37.34 R38.1
  Bottom 0.203: v37.08,29.97 37.85,29.21 40.64,29.21 41.91,27.94 46.48,27.94 55.88,37.34 v58.67,37.34
RF1  (via drill 0.33)
  Top 0.203: IC5.59 36.85,36.34 37.59,37.08 49.28,37.08 50.55,38.35 v54.61,42.42
  Bottom 0.203: J6.9 54.61,49.53 v54.61,42.42
SCK2/RG6  (via drill 0.33)
  Top 0.203: J8.3 63.75,27.94 64.77,28.96 64.77,33.02 63.75,34.04 R37.1 | J5.11 27.69,49.53 27.69,45.72 28.96,44.45 28.96,30.73 30.77,28.92 IC5.4 34.07,28.92 37.85,25.15 v37.85,23.11
  Bottom 0.203: v37.85,23.11 40.39,20.57 46.48,20.57 50.29,24.38 50.29,25.65 51.31,26.67 62.23,26.67 J8.3
SCL1/RG2  (via drill 0.33)
  Top 0.203: JP8.3 64.77,15.24 62.48,15.24 55.63,22.1 v46.48,22.1 | IC5.37 45.69,24.92 v46.48,24.13
  Bottom 0.203: v46.48,24.13 v46.48,22.1
SDA1/RG3  (via drill 0.33)
  Top 0.203: JP6.3 62.48,13.97 55.12,21.34 v45.47,21.34 | IC5.36 45.18,24.42 v45.47,24.13
  Bottom 0.203: v45.47,21.34 v45.47,24.13
SDI2/RG7  (via drill 0.33)
  Top 0.203: IC5.5 33.56,28.42 v37.08,24.89 | JP7.3 53.34,24.13 50.8,24.13 50.29,24.64 50.29,29.97 50.8,30.48 JP5.1
  Bottom 0.203: v37.08,24.89 46.48,24.89 JP5.1
SDO2/RG8  (via drill 0.33)
  Top 0.203: IC5.6 33.29,27.92 36.07,25.15 v36.07,23.11 | JP5.3 50.8,26.67 50.8,28.7 51.31,29.21 53.09,29.21 54.36,30.48 JP7.1
  Bottom 0.203: v36.07,23.11 39.37,19.81 48.01,19.81 52.07,23.88 JP5.3
SS2/RG9  (via drill 0.33)
  Top 0.203: JP4.3 39.37,43.18 34.29,43.18 30.48,39.37 v30.48,31.24 | v30.73,27.18 30.99,26.92 IC5.8 33.53,26.92 34.8,25.65 v34.8,23.11
  Bottom 0.203: v30.73,27.18 30.48,27.43 v30.48,31.24 | v34.8,23.11 38.86,19.05 50.29,19.05 54.1,22.86 JP9.1 JP9.2 J8.5
U1RTS/BCLK1/SCK1/INT0/RF6  (via drill 0.33)
  Top 0.203: IC5.35 42.88,23.92 41.91,24.89 40.89,24.89 40.85,24.94 40.39,25.4 40.39,27.69 38.86,29.21 36.58,29.21 36.32,29.46 36.32,30.23 v36.07,30.48
  Bottom 0.203: v36.07,30.48 36.07,30.99 32.77,34.29 32.77,46.99 J5.10
U1RX/SDI1/RF2  (via drill 0.33)
  Top 0.203: J6.1 64.52,50.8 65.28,50.04 65.28,47.5 49.02,31.24 49.02,24.13 48.31,23.42 IC5.34 42.37,23.42 41.4,24.38 40.64,24.38 39.88,25.15 39.88,26.92 v39.12,27.69 | R1.2 v20.83,37.59
  Bottom 0.203: v39.12,27.69 34.29,27.69 32.51,29.46 32.51,30.48 29.97,33.02 21.59,33.02 20.83,33.78 v20.83,37.59
U1TX/SDO1/RF3  (via drill 0.33)
  Top 0.203: J6.3 62.23,52.07 64.52,52.07 66.04,50.55 66.04,47.5 49.53,30.99 49.53,23.88 48.57,22.92 IC5.33 42.1,22.92 41.15,23.88 40.39,23.88 39.37,24.89 39.37,26.42 v37.34,28.45 | R2.2 v16.01,43.17 v16,43.18 | v16,46.23 16.26,45.97 20.57,45.97 23.11,43.43 v24.38,43.43
  Bottom 0.203: v37.34,28.45 34.8,28.45 33.27,29.97 33.27,30.73 30.48,33.53 30.48,40.39 27.43,43.43 v24.38,43.43 | v16,43.18 v16,46.23
USB5V0  (via drill 0.33)
  Top 0.61: v9.91,36.32 R4.2
  other vias: 6.86,40.39 7.87,40.39 8.89,40.39 11.43,30.48 11.43,29.21 10.16,30.48 10.16,29.21
  pour Top (isolate 0.254, no thermals): 6.35,40.89 9.4,40.89 9.4,39.37 6.35,39.37
  pour Bottom: 5.59,40.89 9.65,40.89 9.65,39.37 8.64,39.37 8.64,37.08 12.7,37.08 12.7,28.45 5.59,28.45
  pour Top: 13.72,31.24 9.4,31.24 9.4,28.45 13.72,28.45
VCC3V3  (via drill 0.33)
  Top 0.203: C15.1 29.22,25.66 v29.21,25.65 | IC5.57 37.85,31.25 v38.1,30.99 | D5.3 54.17,8.95 v54.1,8.89 | D4.6 50.61,8.95 v50.55,8.89 | D4.3 52.51,11.37 v52.58,11.43 | D5.6 56.07,11.37 v56.13,11.43 | D6.6 59.63,11.37 v59.69,11.43 | D6.3 57.72,8.95 v57.66,8.89 | D7.6 61.78,8.95 v61.72,8.89 | LD5.A v64.52,40.64 | LD4.A v64.52,44.2 | R7.2 v20.83,46.48 | R5.2 v20.83,49.53 | D2.2 10.78,44.59 v10.67,44.7 | R13.2 v11.68,46.48 | R9.2 v7.11,1.27
  Top 0.305: IC5.10 30.24,25.92 29.97,25.65 C15.1 | v39.62,17.53 39.62,18.04 C16.1 38.85,18.8 IC5.26 | IC5.38 45.2,25.42 C17.1 45.73,25.66 v45.97,25.65 | IC1.1 16.99,40.87 17.78,41.66 C1.1 18.28,42.17 v18.29,42.16
  Top 0.61: R18.1 v32.51,21.59 | IC4.4 14.1,19.3 9.91,19.3 9.91,16.52 C10.1
  other vias: 10.16,16.51 10.16,15.49 10.16,14.48 11.43,15.49 12.7,15.49
  pour Route2 (isolate 0.254): 0,53.34 68.58,53.34 68.58,0 0,0 0,1.78 13.21,1.78 13.21,12.19 0,12.19
  pour Top (rank 2, no thermals): 9.65,17.27 14.73,17.27 14.73,15.49 13.21,15.49 13.21,12.45 9.65,12.45
VCC5V0  (via drill 0.33)
  Top 0.305: IC1.19 14.49,34.81 14.22,34.54 C2.1
  Top 0.61: C2.1 14.23,33.54 13.97,33.27 13.97,32.52 C3.1
  Top 1.016: C3.1 13.98,30.48 15.49,30.48 15.49,27.18
  Top 1.778: JP2.1 19.81,6.1 24.13,6.1 IC2.2 IC2.TAB
  Bottom 1.016: J2.3 38.1,1.02 19.81,1.02 JP2.1
  other vias: 21.84,14.73 24.89,14.73 23.37,14.73 26.42,14.73
  pour Top (rank 2): 16.26,13.72 16.26,24.13 12.7,24.13 12.7,27.94 17.78,27.94 17.78,21.08 27.18,21.08 27.18,13.72
  pour Bottom: 17.53,19.3 36.83,19.3 36.83,6.35 17.53,6.35
VCMP
  Top 0.406: IC4.3 10.6,23.18 10.41,23.37 D8.3
  Top 0.61: IC4.3 12.18,23.18 R10.2 R8.1
VIN
  Top 0.406: D8.2 8.78,22.72 8.89,22.61 8.89,20.32
  Top 0.61: R8.2 8.89,20.32 8.89,11.18 10.67,11.18 10.67,7.62 J4.1
  Bottom 1.016: JP2.2 22.35,4.32 22.61,4.57
  Bottom 1.778: J2.6 45.72,4.57 22.61,4.57 21.84,5.33 16.51,5.33 14.22,7.62 10.67,7.62
  pour Route2 (no thermals): 9.91,5.59 9.91,9.65 10.41,10.16 10.92,10.16 11.43,9.65 11.43,5.59 10.92,5.08 10.41,5.08
  pour Top (no thermals): 9.91,9.65 10.41,10.16 10.92,10.16 11.43,9.65 11.43,5.59 10.92,5.08 10.41,5.08 9.91,5.59
  pour Route15 (no thermals): 9.91,9.65 10.41,10.16 10.92,10.16 11.43,9.65 11.43,5.59 10.92,5.08 10.41,5.08 9.91,5.59
  pour Bottom (no thermals): 9.91,9.65 10.41,10.16 10.92,10.16 11.43,9.65 11.43,5.59 10.92,5.08 10.41,5.08 9.91,5.59
VREF+/AN0
  Top 0.203: J5.15 22.61,49.53 R19.2
VREF-/AN1
  Top 0.203: R20.2 J5.16

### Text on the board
tPlace: RESET | A | G | 9 | 8 | 7 | 6 | 5 | 4 | 3 | 2 | 1 | 0 | 13 | 12 | 11 | 10 | 41 | 40 | 39 | 38 | 37 | 36 | 35 | 34 | 33 | 32 | 31 | 30 | 29 | 28 | TX | RX | 1 | PWM/DIGITAL | 27 | 26 | RD4 | 10 | RG9 | MASTER | 1 | 1 | SPI | SPI | SELECT | SLAVE | ANALOG | A4 | A5 | ICSP | A6 | A7 | A8 | A9 | A10 | A11 | RG3 | RG2 | 15V MAX! | A0 | A1 | A2 | A3 | A4 | A5 | - | POWER | POWER | + | SELECT | BYP | REG | RESET | 3V3 | 5V0 | GND | GND | VIN
bPlace: REV C | PB200-209
Measures: 0.6" | 2.1" | 2.0" | 1.4" | Slot Drills | 0.026 x 0.125" | 0.3" | 0.1" | 0.55" | 2.6" | 2.7"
